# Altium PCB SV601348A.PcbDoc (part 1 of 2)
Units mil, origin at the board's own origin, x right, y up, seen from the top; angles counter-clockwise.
Board outline 3650 x 3650 mil, 6 copper layers (Top Layer, MidLayer1, MidLayer2, MidLayer3, MidLayer4, Bottom Layer), stack 60.8 mil thick; 120 components, 45 nets, 333 pads, 436 vias.
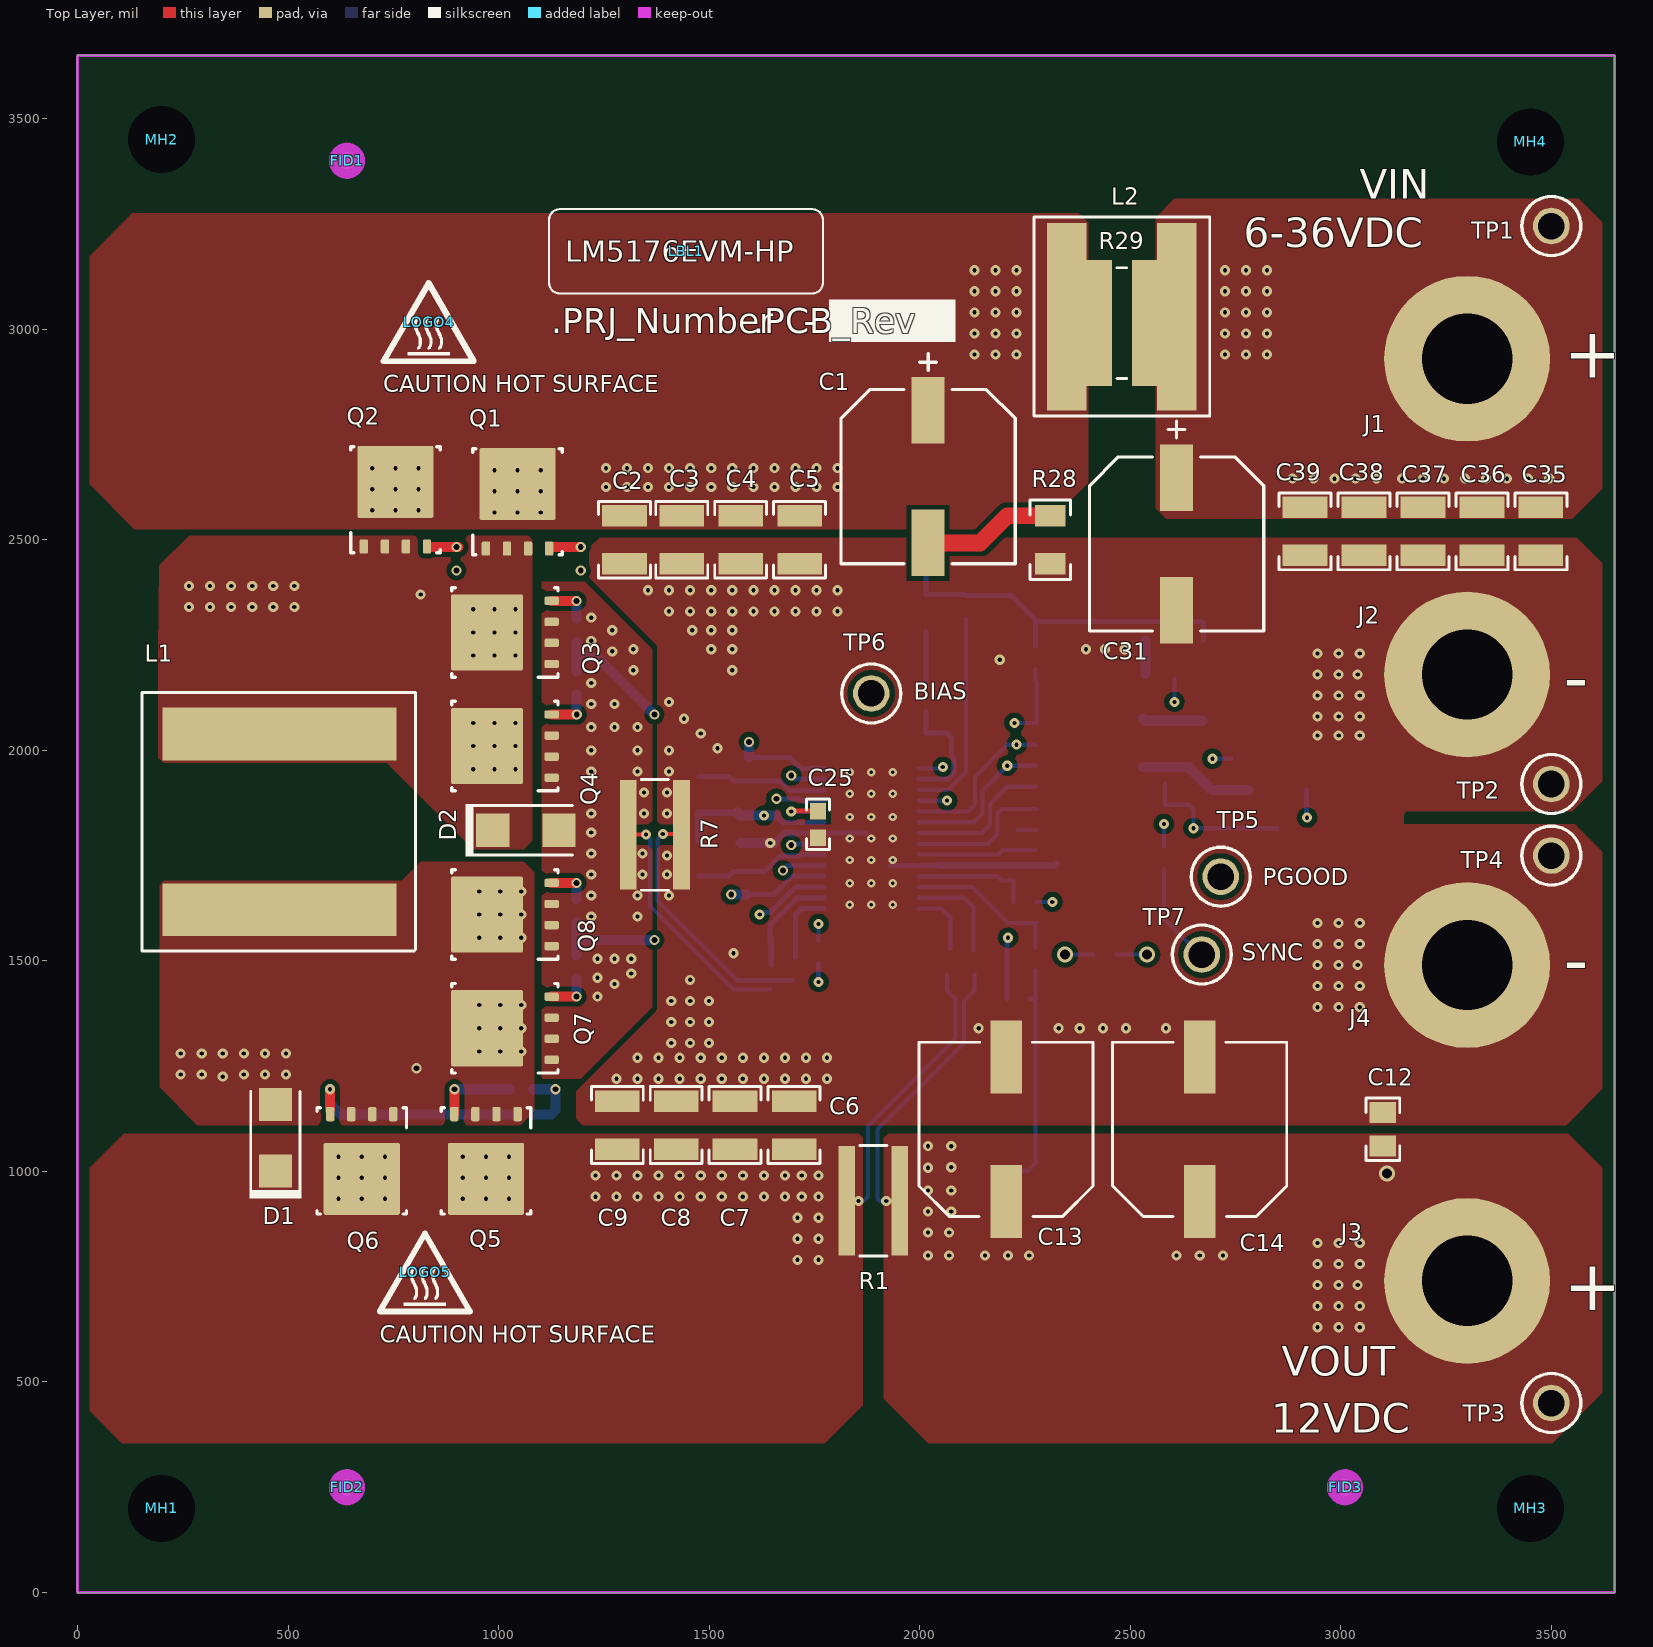
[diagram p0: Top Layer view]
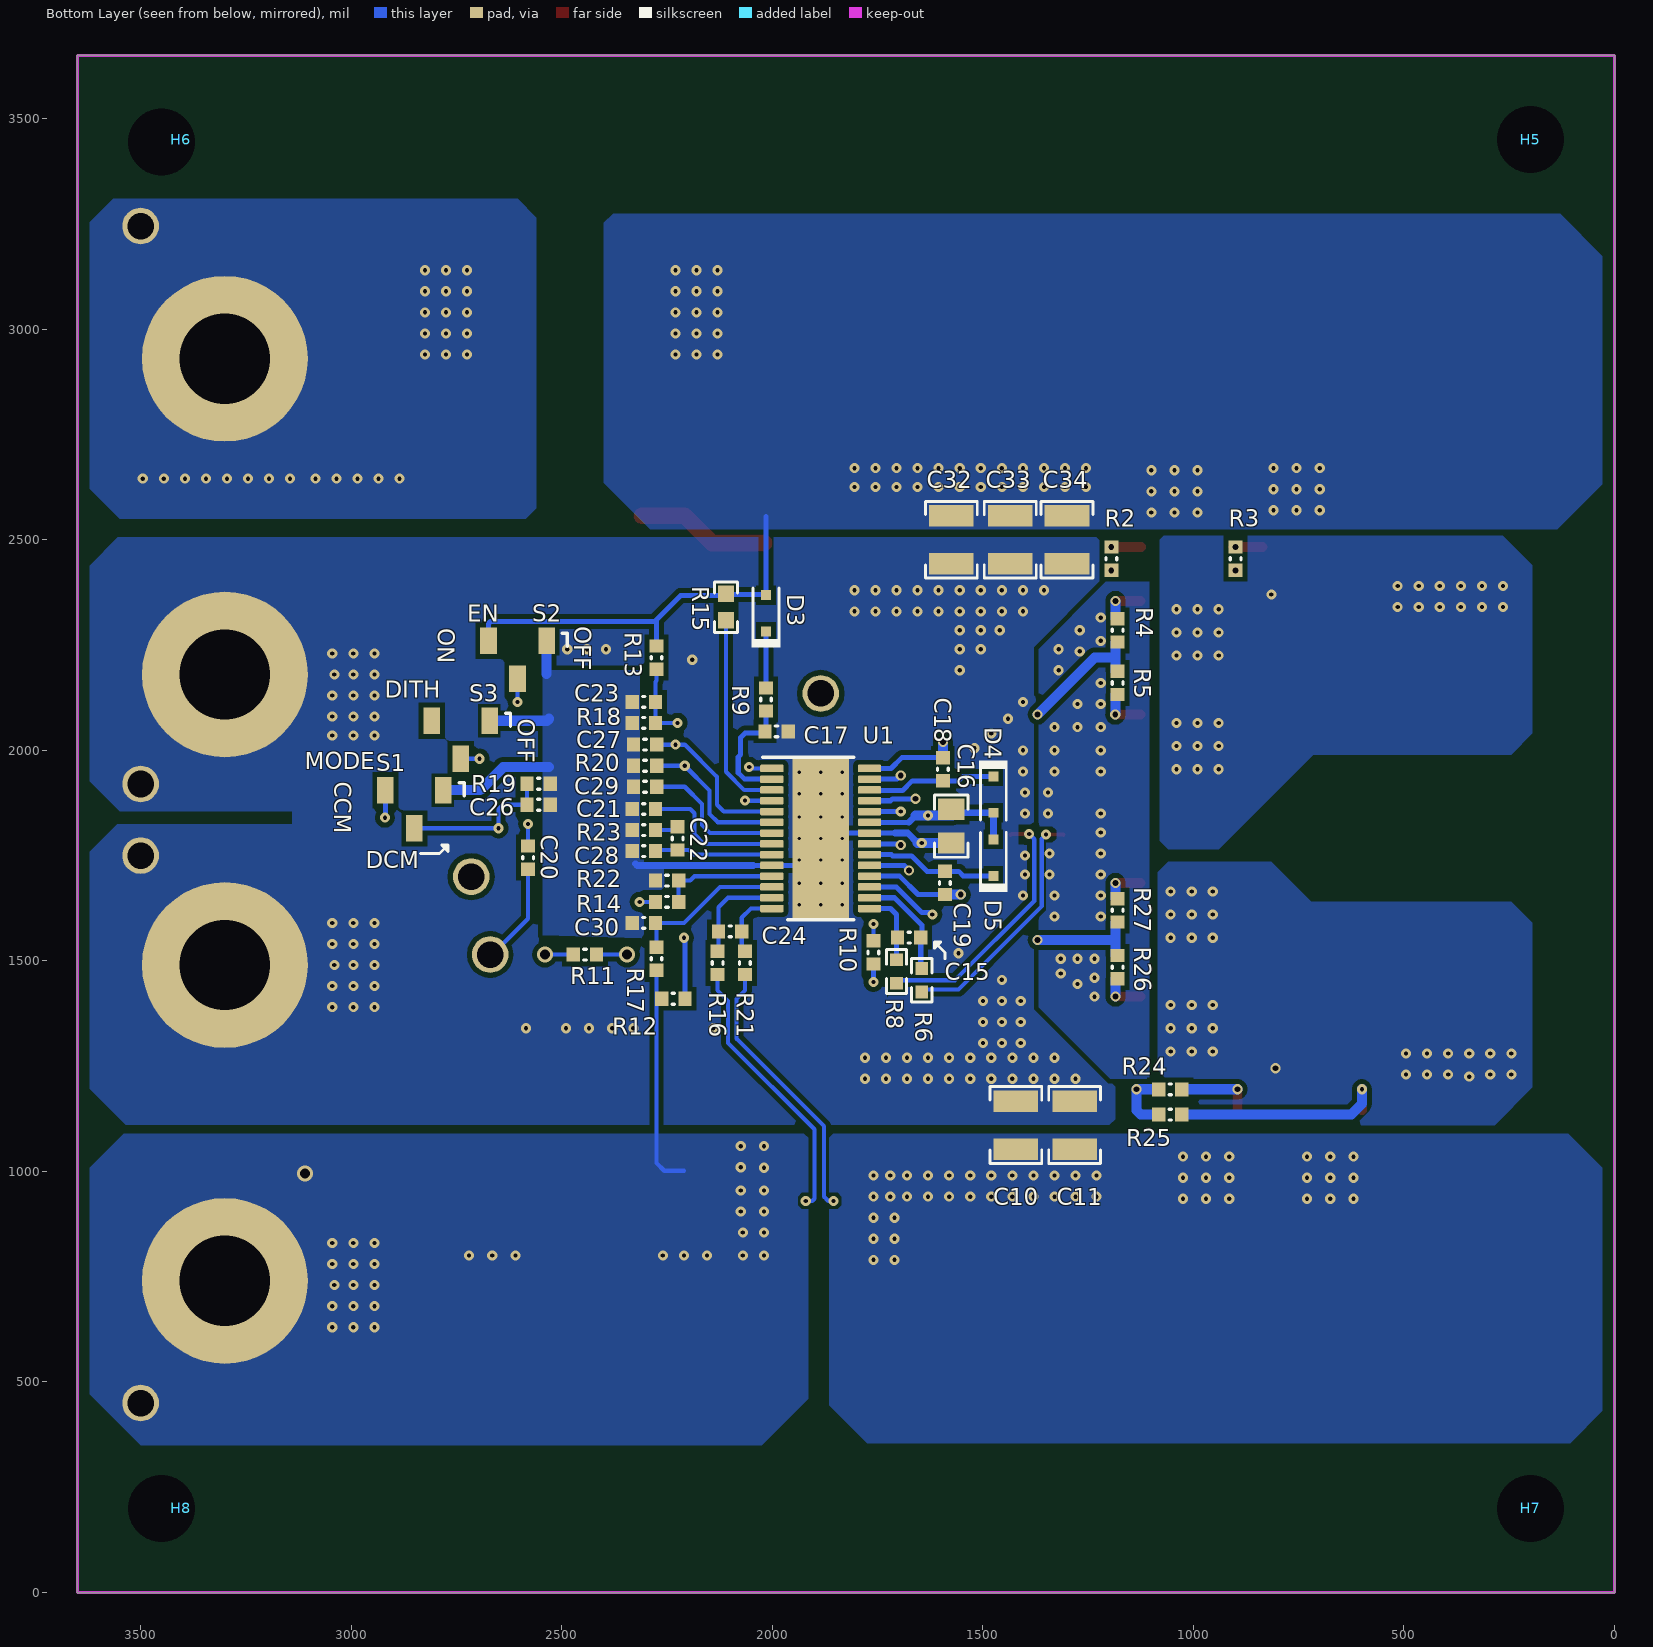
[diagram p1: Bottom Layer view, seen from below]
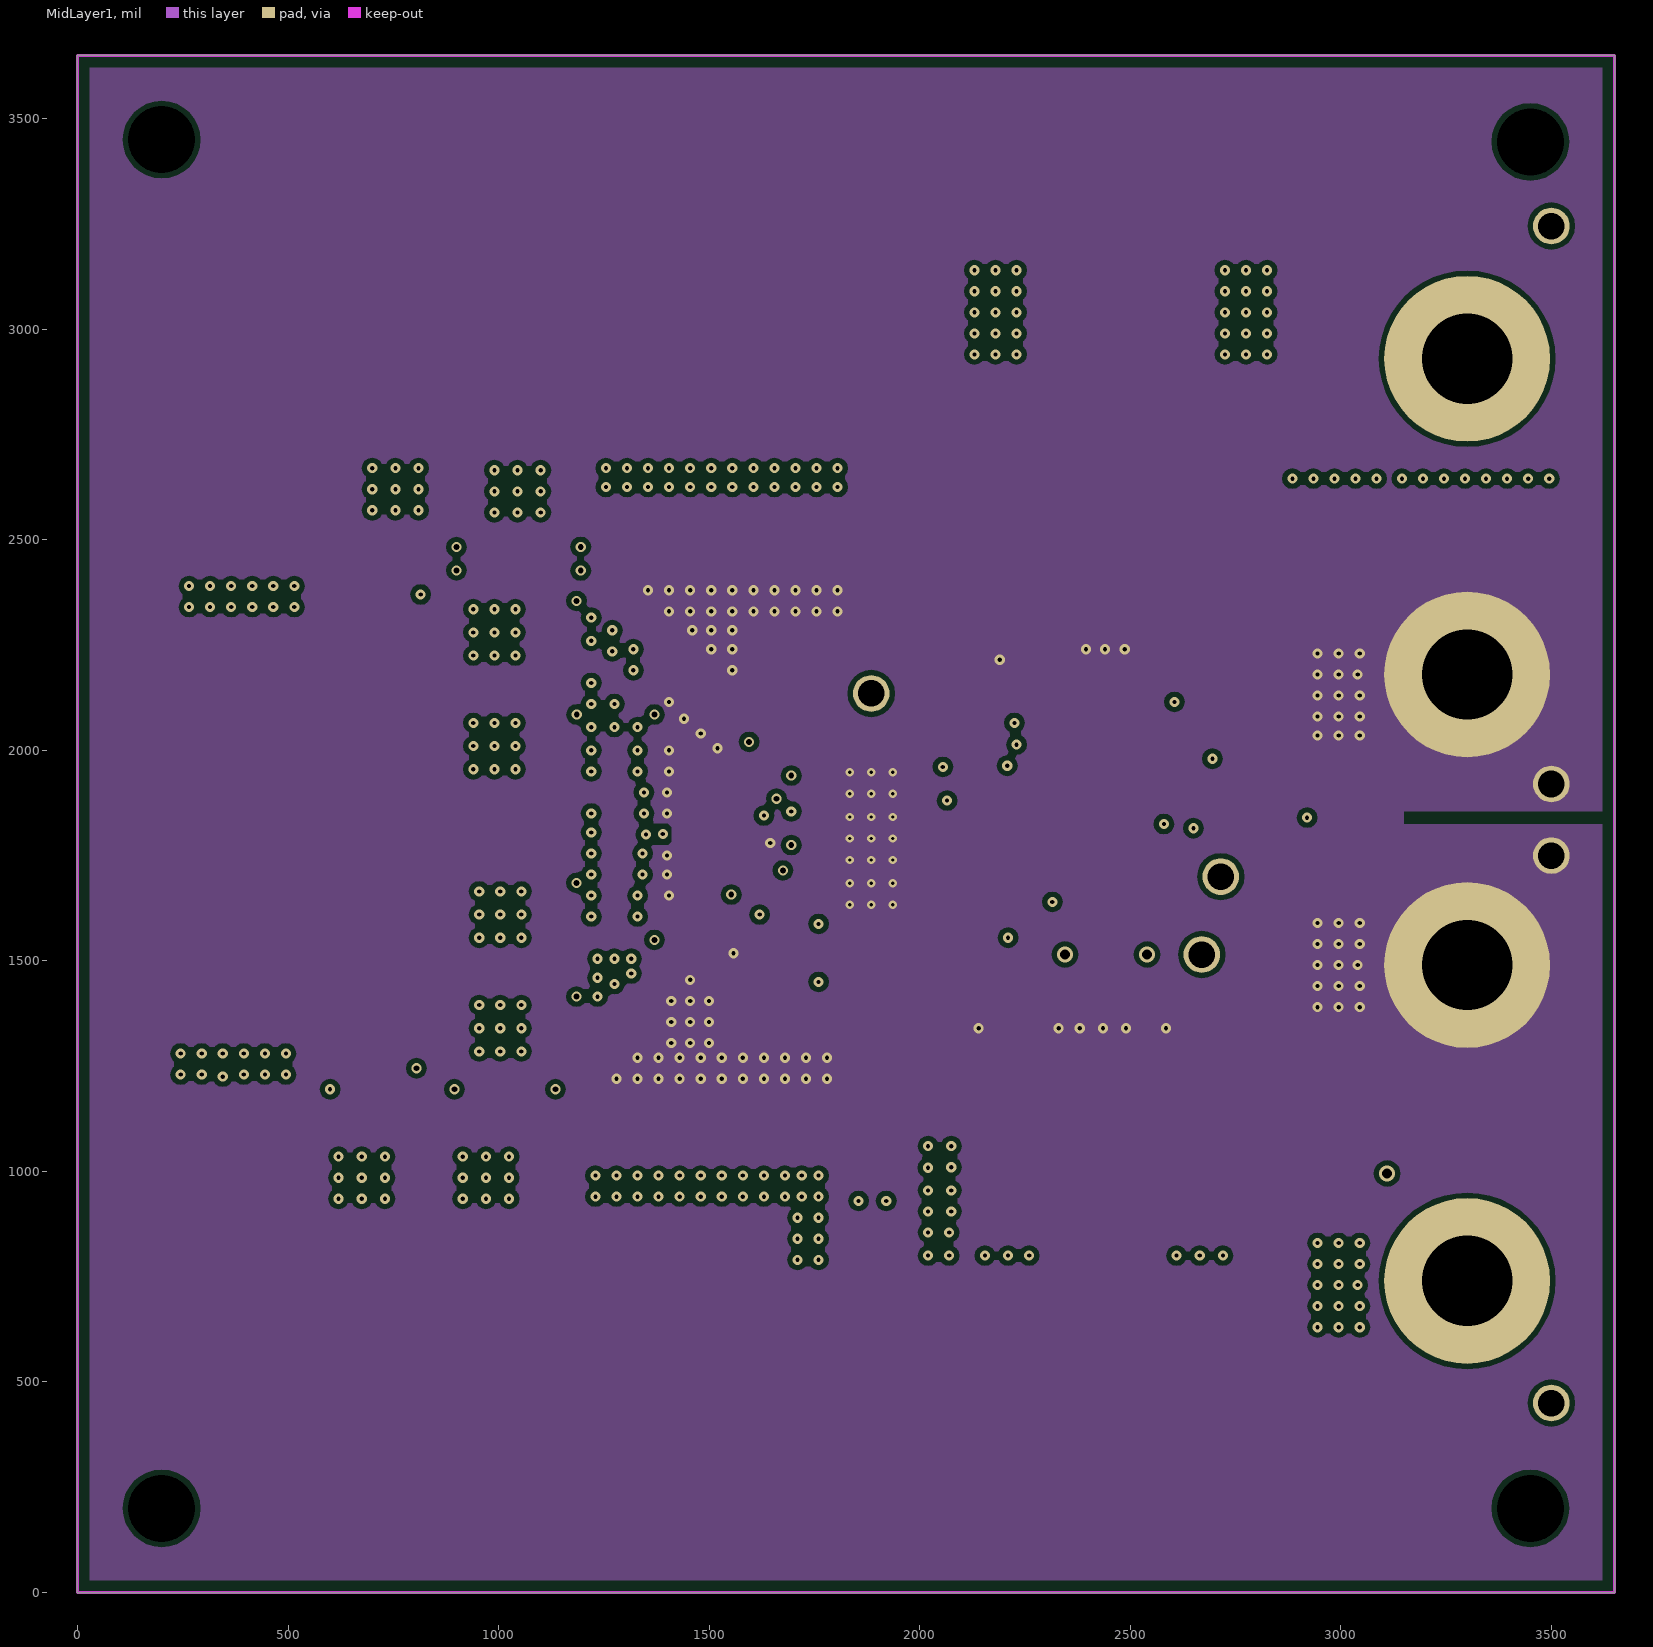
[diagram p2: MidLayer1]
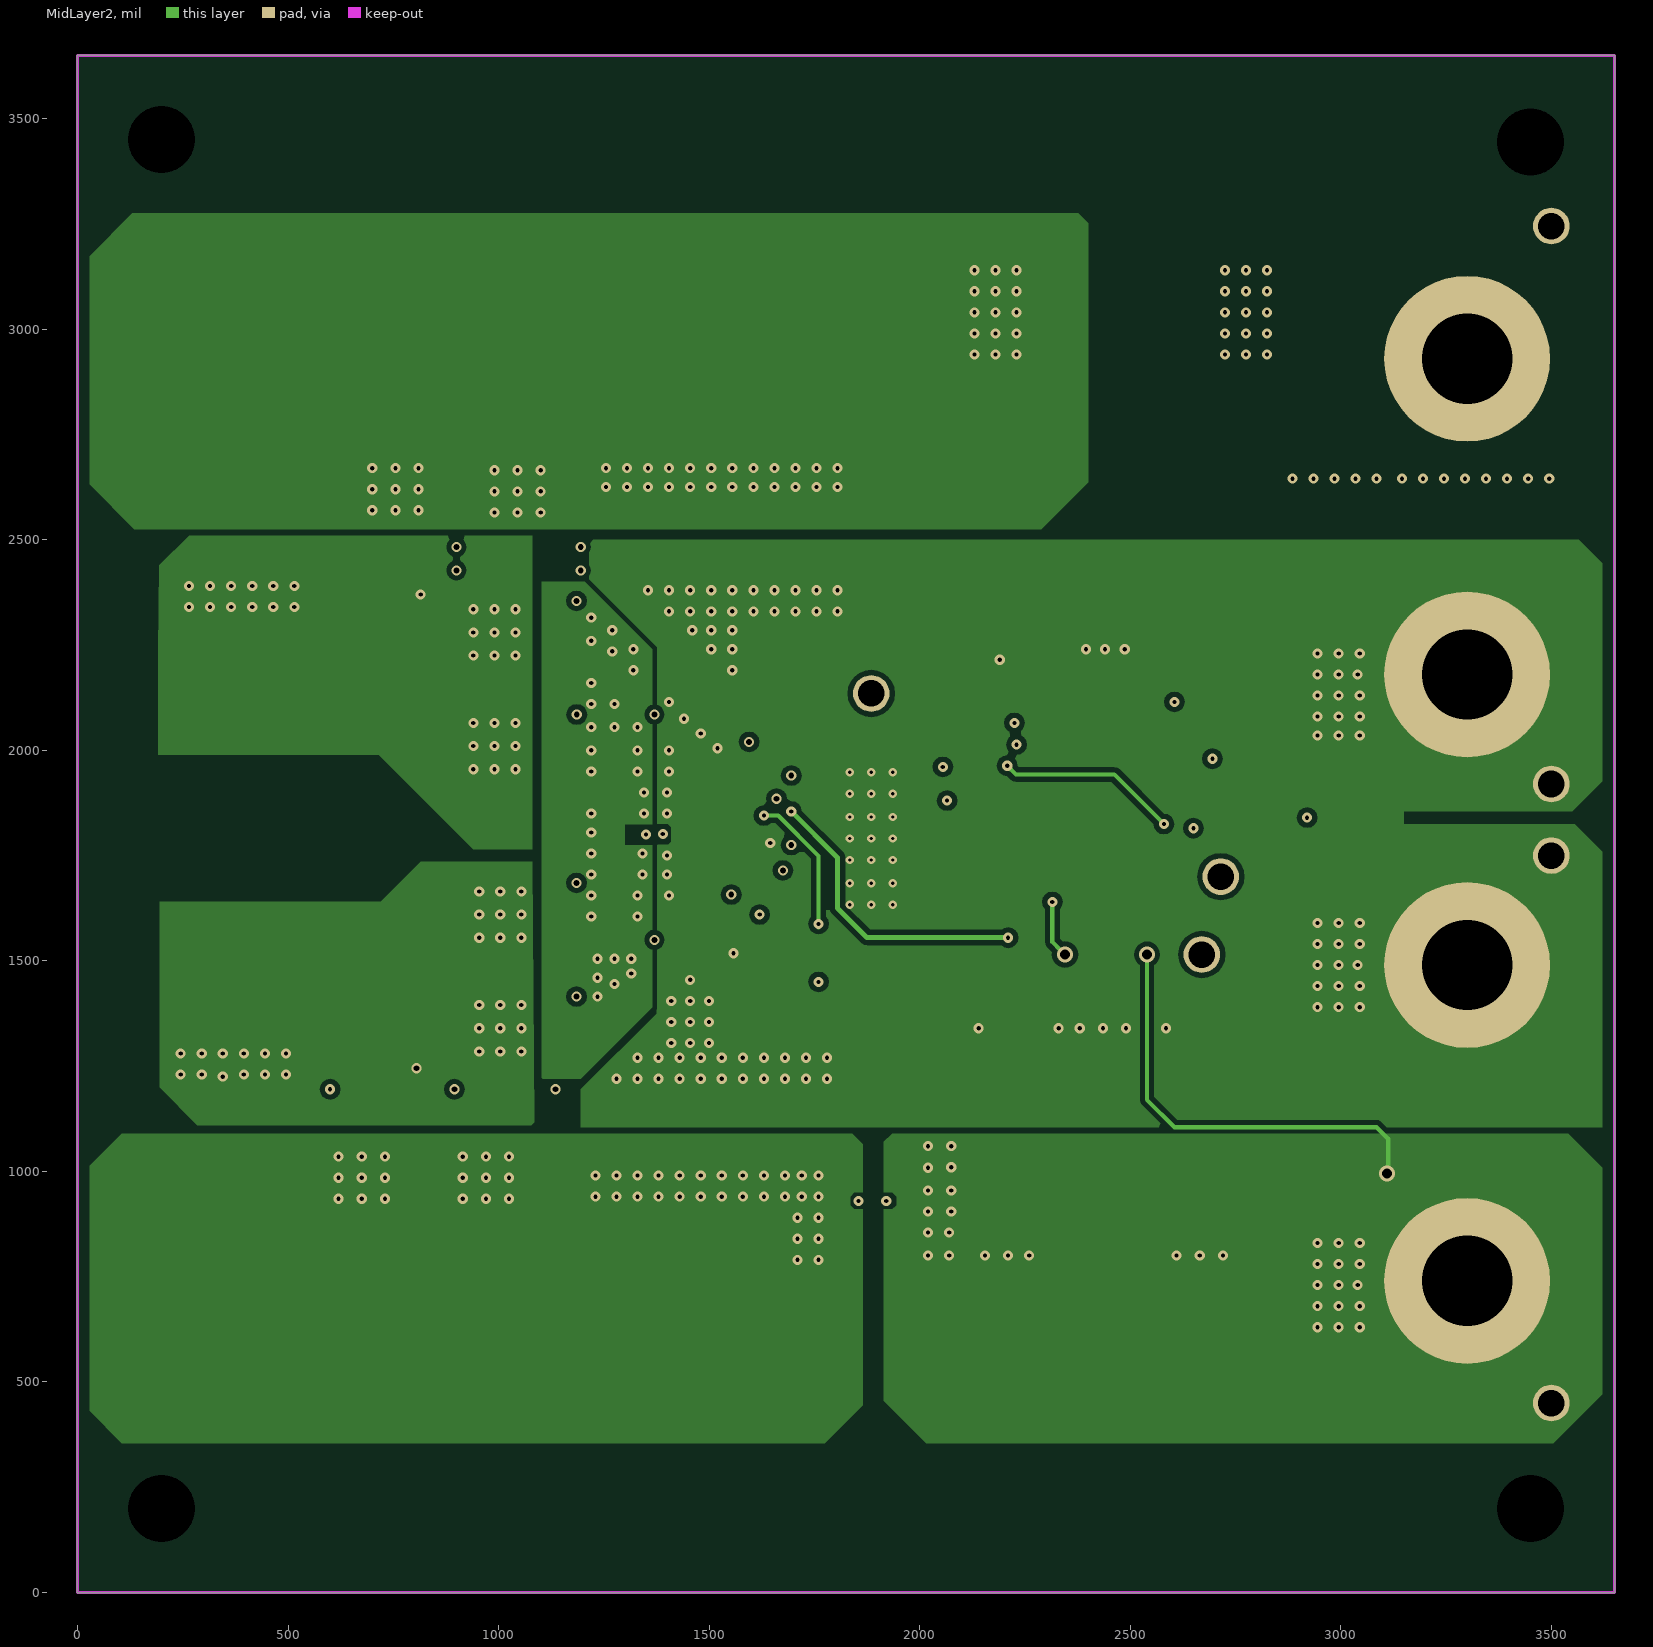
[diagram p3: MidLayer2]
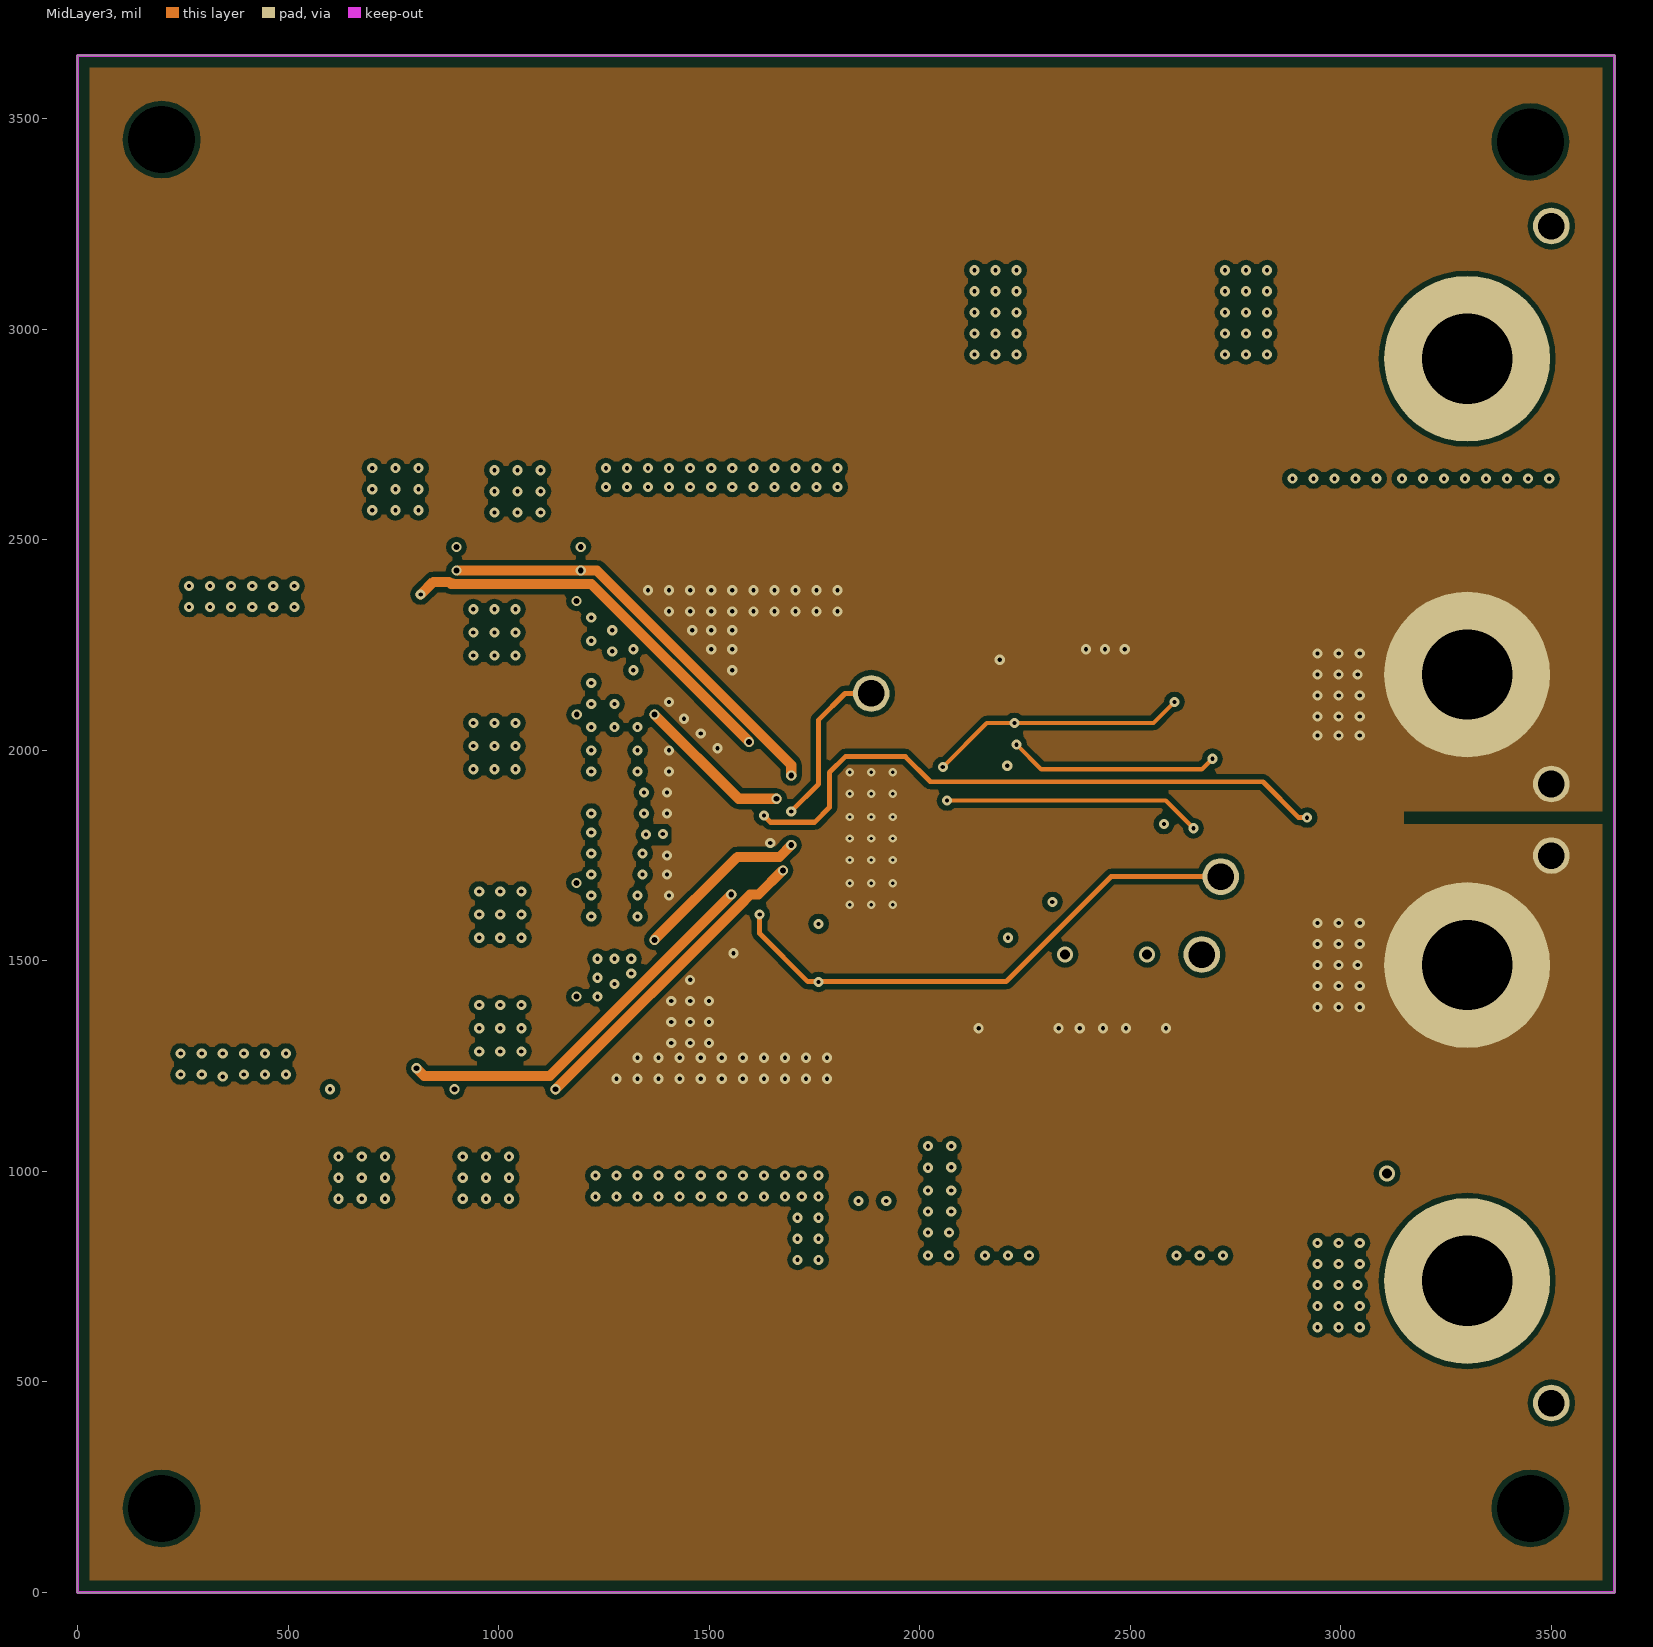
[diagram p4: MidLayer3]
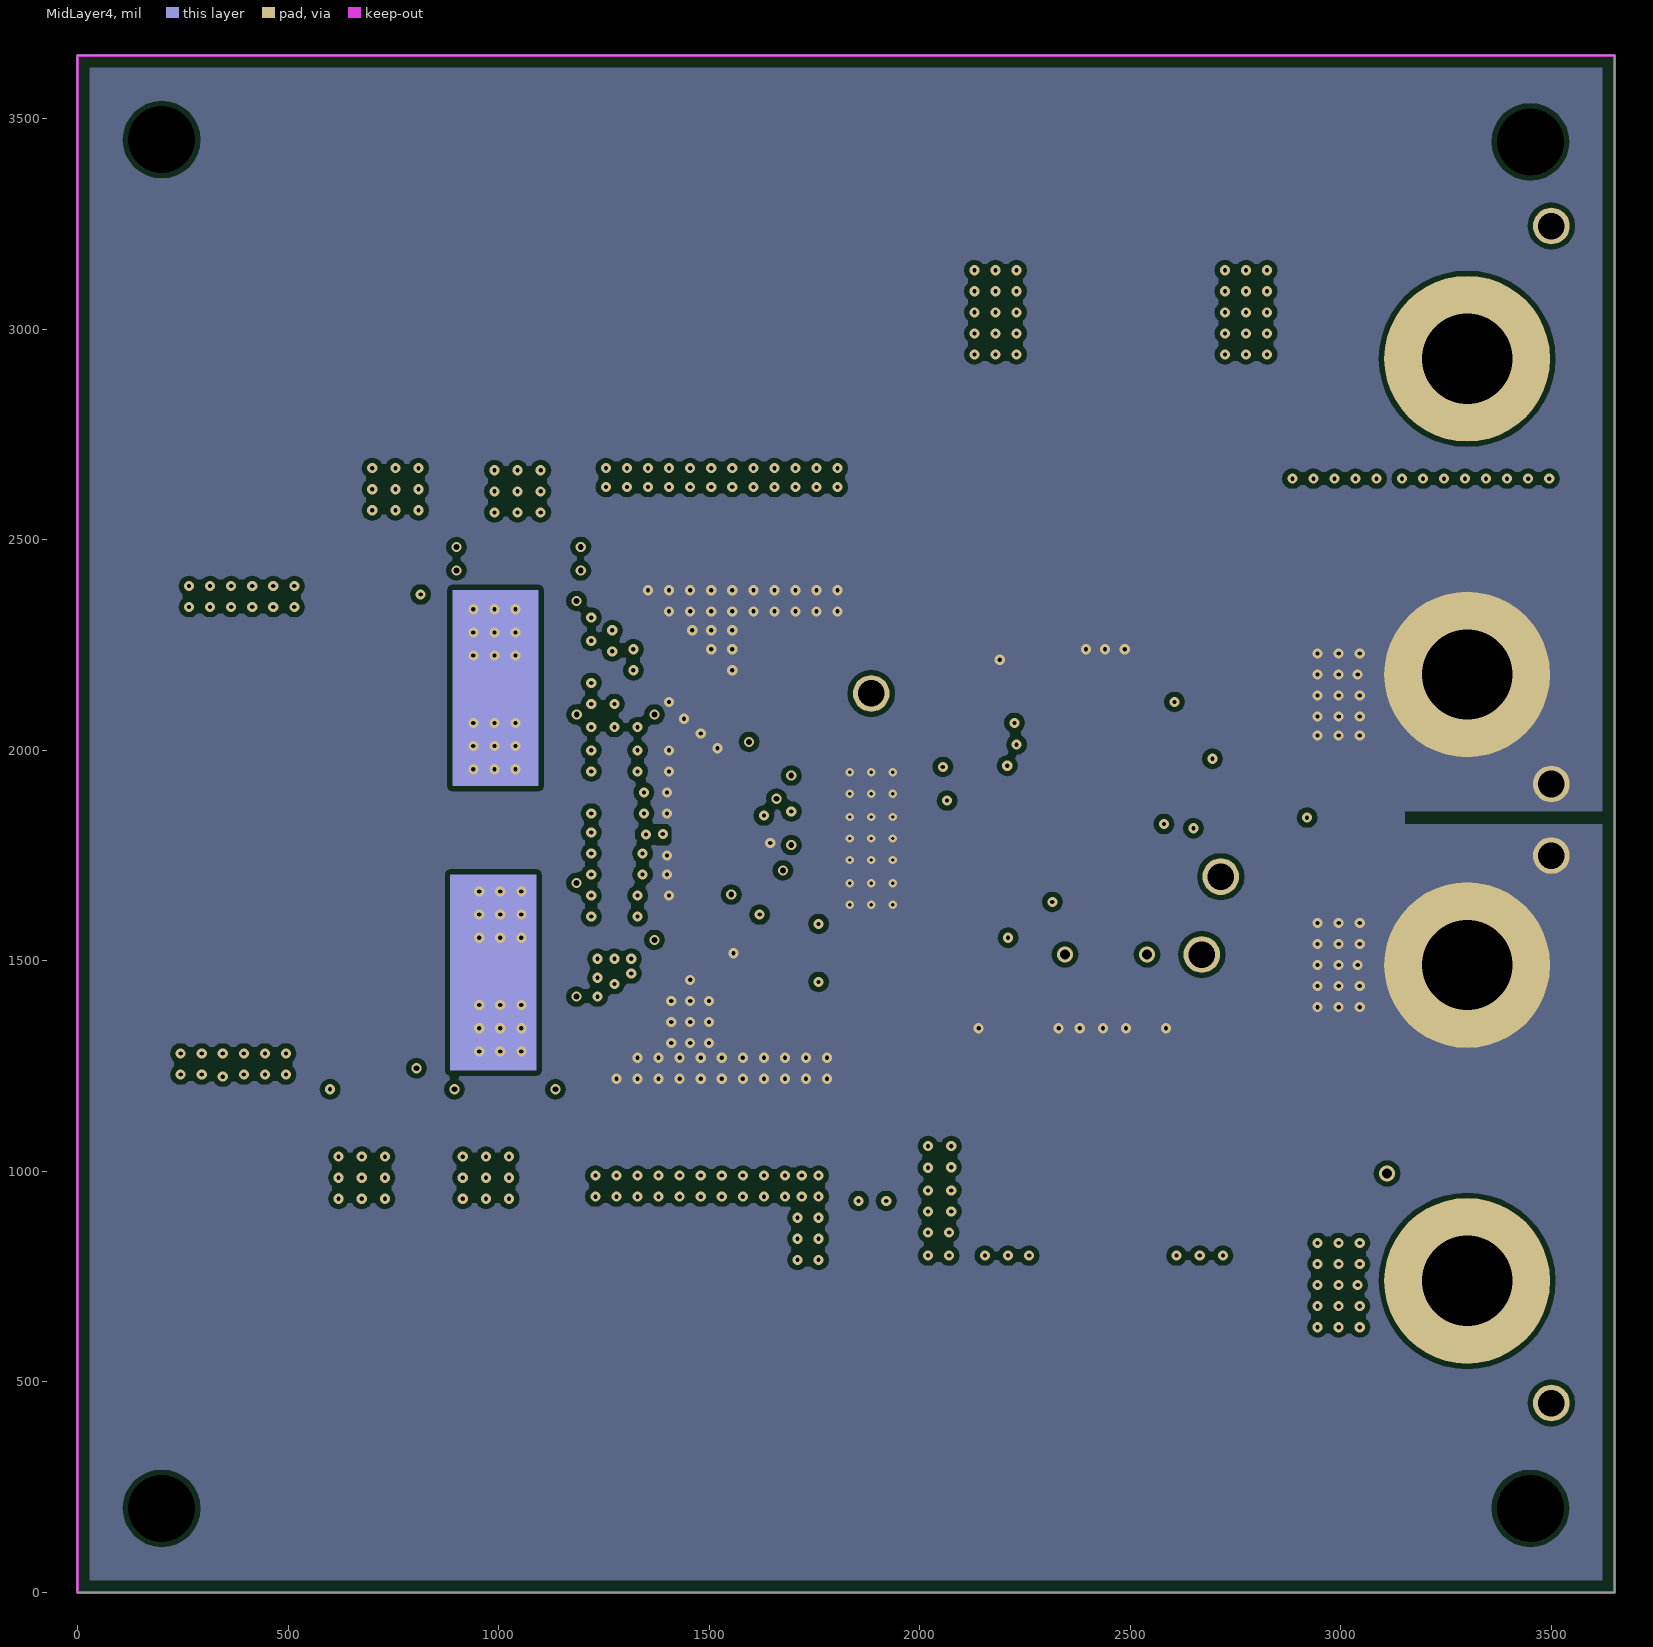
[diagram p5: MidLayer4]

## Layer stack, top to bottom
Top Solder: solder mask 0.4, Solder Resist, Dk 3.5
Top Layer: signal copper 2.8
Dielectric1: prepreg 8, FR-4, Dk 4.2
MidLayer1: signal copper 2.8
Dielectric2: prepreg 8, FR-4, Dk 4.8
MidLayer2: signal copper 2.8
Dielectric3: prepreg 12, FR-4, Dk 4.2
MidLayer3: signal copper 2.8
Dielectric4: prepreg 8, FR-4, Dk 4.8
MidLayer4: signal copper 2.8
Dielectric5: core 8, FR-4, Dk 4.8
Bottom Layer: signal copper 2.8
Bottom Solder: solder mask 0.4, Solder Resist, Dk 3.5

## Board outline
0,0 3650,0 3650,3650 0,3650

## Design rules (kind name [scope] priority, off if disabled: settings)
AcuteAngle [All] p1: minimum=4.50000000000000E+0001 checktracksonly=FALSE
AssemblyTestPointUsage [All] p1: valid=2
Clearance Clearance_BoardEdge_MountingHoles [OnCopper and InComponentClass('Mounting Holes') vs KeepOut] p1: gap=40 ignorepadtopadclearanceinfootprint=FALSE except(0: Arc-Hole Track-Hole SMDPad-Hole THPad-Hole Via-Hole Fill-Hole Poly-Hole Region-Hole Text-Hole)
Clearance Clearance_BoardEdge_Poly [OnCopper and InPoly vs KeepOut] p2: gap=25 ignorepadtopadclearanceinfootprint=FALSE except(0: Arc-Hole Track-Hole SMDPad-Hole THPad-Hole Via-Hole Fill-Hole Poly-Hole Region-Hole Text-Hole)
Clearance Clearance_BoardEdge [OnCopper and Not InComponentClass('Logo') and not InComponentClass('FiducialMark') and not InRegion(1000,500,4000,800) and Not IsKeepout vs KeepOut] p3: gap=47 ignorepadtopadclearanceinfootprint=FALSE except(0: Arc-Hole Track-Hole SMDPad-Hole THPad-Hole Via-Hole Fill-Hole Poly-Hole Region-Hole Text-Hole)
Clearance Clearance_Poly [InPolygon] p4: gap=12 ignorepadtopadclearanceinfootprint=FALSE except(0: Arc-Hole Track-Hole SMDPad-Hole THPad-Hole Via-Hole Fill-Hole Poly-Hole Region-Hole Text-Hole)
Clearance Clearance_FiducialMark [IsKeepOut and InComponentClass('FiducialMark') vs IsPad and InComponentClass('FiducialMark')] p5: gap=0 ignorepadtopadclearanceinfootprint=FALSE
Clearance [All] p6: gap=7.87 ignorepadtopadclearanceinfootprint=FALSE except(0: Arc-Hole Track-Hole SMDPad-Hole THPad-Hole Via-Hole Fill-Hole Poly-Hole Region-Hole Text-Hole)
ComponentClearance ComponentClearance_EMI-Shunt [InComponent('L2') vs InComponent('R29')] p1: gap=0 collisioncheckmode=3 verticalgap=0 showdistances=FALSE
ComponentClearance ComponentClearance_Shunt [InComponentClass('Header') vs InComponentClass('Shunt')] p2: gap=0 collisioncheckmode=3 verticalgap=0 showdistances=FALSE
ComponentClearance ComponentClearance_MountingHoles_FiducialMarks [InComponentClass('Mounting Holes') vs InComponentClass('FiducialMark')] p3: gap=42 collisioncheckmode=3 verticalgap=10 showdistances=FALSE
ComponentClearance ComponentClearance_Logo [InComponentClass('Logo')] p4: gap=50 collisioncheckmode=3 verticalgap=10 showdistances=FALSE
ComponentClearance ComponentClearance_ScrewToNut [(HasFootprint('NY PMS 440 0025 PH')) vs (HasFootprint('Keystone_1902C'))] p5: gap=5 collisioncheckmode=3 verticalgap=10 showdistances=FALSE
ComponentClearance ComponentClearance_MountingHoles [InComponentClass('Mounting Holes')] p6: gap=200 collisioncheckmode=3 verticalgap=100000 showdistances=FALSE
ComponentClearance ComponentClearance_SmallPassives [HasFootprint('0201*') or HasFootprint('0402*') or HasFootprint('0508') or HasFootprint('0603*') or HasFootprint('0612') or HasFootprint('0805*') or HasFootprint('0815*') or HasFootprint('0830*') or HasFootprint('1206*') or HasFootprint('1210*') or HasFootprint('1808*') or HasFootprint('1812*') or HasFootprint('1825*') or HasFootprint('2010*') or HasFootprint('2220*') or HasFootprint('2225*') or HasFootprint('2512*') or HasFootprint('2728*') or HasFootprint('3518*') vs HasFootprint('0201*') or HasFootprint('0402*') or HasFootprint('0508') or HasFootprint('0603*') or HasFootprint('0612') or HasFootprint('0805*') or HasFootprint('0815*') or HasFootprint('0830*') or HasFootprint('1206*') or HasFootprint('1210*') or HasFootprint('1808*') or HasFootprint('1812*') or HasFootprint('1825*') or HasFootprint('2010*') or HasFootprint('2220*') or HasFootprint('2225*') or HasFootprint('2512*') or HasFootprint('2728*') or HasFootprint('3518*')] p7: gap=10 collisioncheckmode=3 verticalgap=10 showdistances=FALSE
ComponentClearance ComponentClearance_THtoSMT [IsThruComponent vs IsSMTComponent] p8: gap=40 collisioncheckmode=3 verticalgap=30 showdistances=FALSE
ComponentClearance ComponentClearance_THtoTH [IsThruComponent vs IsThruComponent] p9: gap=25 collisioncheckmode=3 verticalgap=15 showdistances=FALSE
ComponentClearance [All] p10: gap=40 collisioncheckmode=3 verticalgap=10 showdistances=FALSE
DiffPairsRouting [All] p1: maxlimit=100 minlimit=10 mostfreqgap=10 toplayer_minwidth=15 toplayer_maxwidth=15 toplayer_prefwidth=15 midlayer1_minwidth=15 midlayer1_maxwidth=15 midlayer1_prefwidth=15 midlayer2_minwidth=15 midlayer2_maxwidth=15 midlayer2_prefwidth=15 midlayer3_minwidth=15 midlayer3_maxwidth=15 midlayer3_prefwidth=15 midlayer4_minwidth=15 midlayer4_maxwidth=15 midlayer4_prefwidth=15 bottomlayer_minwidth=15 bottomlayer_maxwidth=15 bottomlayer_prefwidth=15 maxuncoupledlength=1000
FabricationTestPointUsage TestPointUsage [All] p1: valid=2 allowmultiple=FALSE
FabricationTestpoint Testpoint [All] p1: side=3 testpointundercomponent=TRUE minsize=40 maxsize=100 preferedsize=60 minholesize=0 maxholesize=40 preferedholesize=32 testpointgrid=1 allowsidetop=TRUE allowsidebottom=TRUE usegrid=TRUE gridtolerance=0.01
FanoutControl Fanout_LCC [IsLCC] p1: bgadir=Out bgaviamode=Centered fanoutstyle=Auto fanoutdirection=Alternating viagrid=1 // Fanout_LCC (Default Rule)
FanoutControl Fanout_BGA [IsBGA] p2: bgadir=Out bgaviamode=Centered fanoutstyle=Auto fanoutdirection=Alternating viagrid=1 // Fanout_BGA (Default Rule)
FanoutControl Fanout_Default [All] p4: bgadir=Out bgaviamode=Centered fanoutstyle=Auto fanoutdirection=Alternating viagrid=1 // Fanout_Default (Default Rule)
FanoutControl Fanout_Small [(CompPinCount < 5)] p5: bgadir=Out bgaviamode=Centered fanoutstyle=Auto fanoutdirection=OutThenIn viagrid=1 // Fanout_Small (Default Rule)
HoleSize [All] p1: absolutevalues=TRUE maxlimit=280 minlimit=7.87 maxpercent=80.000 minpercent=20.000
MinimumAnnularRing MinimumAnnularRing_ThermalPadVias [IsVia and InAnyComponent] p1: minimumring=3.94
MinimumAnnularRing [All] p2: minimumring=5
MinimumSolderMaskSliver MinimumSolderMaskSliver_FET [HasFootprint('DNK0008A')] p1: minsoldermaskwidth=0
MinimumSolderMaskSliver MinimumSolderMaskSliver_Logo [InComponentClass('Logo') vs InComponentClass('Logo')] p2: minsoldermaskwidth=0.7
MinimumSolderMaskSliver [All] p3: minsoldermaskwidth=3.94
PlaneConnect [All] p1: planeconnectstyle=Relief reliefexpansion=10 reliefentries=4 reliefconductorwidth=10 reliefairgap=10
PolygonConnect [All] p1: connectstyle=Direct reliefconductorwidth=10 reliefentries=4 polygonreliefangle="90 Angle" airgapwidth=10
RoutingVias ThermalPadVias [IsVia and InAnyComponent] p1: holewidth=7.87 width=19.68 viastyle="Through Hole" minholewidth=7.87 minwidth=15.75 maxholewidth=12.99 maxwidth=23.62
RoutingVias [All] p2: holewidth=10 width=24 viastyle="Through Hole" minholewidth=7.87 minwidth=13.78 maxholewidth=40 maxwidth=65
SMDToCorner [All] p1: distance=30000
SilkToBoardRegionClearance [NOT ((IsComment OR IsDesignator) AND (Hide <> 'FAIL')) AND NOT InRegion (100,500,4000,800)] p1:
SilkToSilkClearance SilkToSilkClearance_PbFree [HasFootprint('Pb-Free_Overlay_Small')] p1: silktosilkclearance=0
SilkToSilkClearance [All] p2: silktosilkclearance=5
SilkToSolderMaskClearance SilkscreenOverComponentPads [IsPad] p1: minsilkscreentomaskgap=5 clearancetoexposedcopper=TRUE
SolderMaskExpansion [All] p1: expansion=1.97
Width [All] p1: maxlimit=100 minlimit=6 preferedwidth=10 checkconnectedcopper=TRUE
15 further rules are at their usual default settings.

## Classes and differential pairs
component class SV601348A-HW: FID1 FID2 FID3 H5 H6 H7 H8 LBL1 LOGO4 LOGO5 MH1 MH2 MH3 MH4 ZZ1 ZZ2 ZZ3 ZZ4 ZZ5 ZZ6 ZZ7 ZZ8
component class FiducialMark: FID1 FID2 FID3
component class AssemblyNote: ZZ1 ZZ2 ZZ3 ZZ4 ZZ5 ZZ6 ZZ7 ZZ8
component class Label: LBL1
component class SV601348A: C1 C2 C3 C4 C5 C6 C7 C8 C9 C10 C11 C12 C13 C14 C15 C16 C17 C18 C19 C20 C21 C22 C23 C24 C25 C26 C27 C28 C29 C30 C31 C32 C33 C34 C35 C36 C37 C38 C39 D1 D2 D3 D4 D5 J1 J2 J3 J4 L1 L2 Q1 Q2 Q3 Q4 Q5 Q6 Q7 Q8 R1 R2 R3 R4 R5 R6 R7 R8 R9 R10 R11 R12 R13 R14 R15 R16 R17 R18 R19 R20 R21 R22 R23 R24 R25 R26 R27 R28 R29 S1 S2 S3 TP1 TP2 TP3 TP4 TP5 TP6 TP7 U1

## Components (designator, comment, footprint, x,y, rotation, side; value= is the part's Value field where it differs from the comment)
C1 "PCR1J101MCL1GS" CR_1000x1270 2020,2650 r270 top value=100uF
C2 "GRM32ER71K475KE14L" 1210_270 1298.7,2500 r270 top value=4.7uF
C3 "GRM32ER71K475KE14L" 1210_270 1435,2500 r270 top value=4.7uF
C4 "GRM32ER71K475KE14L" 1210_270 1575,2500 r270 top value=4.7uF
C5 "GRM32ER71K475KE14L" 1210_270 1715,2500 r270 top value=4.7uF
C6 "GRM32ER71E226KE15L" 1210_270 1701.85,1110 r90 top value=22uF
C7 "GRM32ER71E226KE15L" 1210_270 1561.54,1110 r90 top value=22uF
C8 "GRM32ER71E226KE15L" 1210_270 1421.85,1110 r90 top value=22uF
C9 "GRM32ER71E226KE15L" 1210_270 1281.85,1110 r90 top value=22uF
C10 "GRM32ER71E226KE15L" 1210_270 1421.85,1110 r90 bottom value=22uF
C11 "GRM32ER71E226KE15L" 1210_270 1281.85,1110 r90 bottom value=22uF
C12 "GRM219R71E105KA88D" 0805_HV 3100,1100 r90 top value=1uF
C13 "16SVP330M" SM_RADIAL_10AMM 2205,1100 r90 top value=330uF
C14 "16SVP330M" SM_RADIAL_10AMM 2665,1100 r90 top value=330uF
C15 "GRM1885C1H470JA01D" 0603L 1675,1555 r0 bottom value=47pF
C16 "GRM21BR71C475KA73L" 0805_HV 1575,1820 r90 bottom value=4.7uF
C17 "GRM188R72A104KA35D" 0603L 1990,2045 r180 bottom value=0.1uF
C18 "GRM188R71E224KA88D" 0603L 1595,1955 r270 bottom value=0.22uF
C19 "GRM188R71E224KA88D" 0603L 1590,1685 r270 bottom value=0.22uF
C20 "GRM1885C2A101JA01D" 0603L 2580,1745 r90 bottom value=100pF
C21 "GRM188R72A104KA35D" 0603L 2305,1860.63 r0 bottom value=0.1uF
C22 "GRM188R71H333KA61D" 0603L 2225,1790.63 r90 bottom value=0.033uF
C23 "47pF" 0603L 2305,2115 r0 bottom
C24 "GRM188R71C334KA01D" 0603L 2100,1570 r180 bottom value=0.33uF
C25 "GRM188R71E224KA88D" 0603 1758.62,1824.19 r270 top value=0.22uF
C26 "47pF" 0603L 2555,1870.63 r180 bottom
C27 "C0603C223K5RACTU" 0603L 2302.2,2013.43 r0 bottom value=0.022uF
C28 "GRM1885C2A102JA01D" 0603L 2305,1760.63 r0 bottom value=1000pF
C29 "GRM1885C1H271JA01D" 0603L 2302.2,1913.43 r0 bottom value=270pF
C30 "GRM1885C2A101JA01D" 0603L 2305,1590 r0 bottom value=100pF
C31 "PCR1J101MCL1GS" CR_1000x1270 2610,2490 r270 top value=100uF
C32 "GRM32ER71K475KE14L" 1210_270 1575,2500 r270 bottom value=4.7uF
C33 "GRM32ER71K475KE14L" 1210_270 1435,2500 r270 bottom value=4.7uF
C34 "GRM32ER71K475KE14L" 1210_270 1300,2500 r270 bottom value=4.7uF
C35 "GRM32ER71K475KE14L" 1210_270 3475,2520 r270 top value=4.7uF
C36 "GRM32ER71K475KE14L" 1210_270 3335,2520 r270 top value=4.7uF
C37 "GRM32ER71K475KE14L" 1210_270 3195,2520 r270 top value=4.7uF
C38 "GRM32ER71K475KE14L" 1210_270 3055,2520 r270 top value=4.7uF
C39 "GRM32ER71K475KE14L" 1210_270 2915,2520 r270 top value=4.7uF
D1 "20V" SMA 470,1080 r90 top
D2 "60V" SMA 1065,1810 r0 top
D3 "60V" SOD-323F 2015,2325 r90 bottom
D4 "100V" sod-323 1475,1895 r270 bottom
D5 "100V" sod-323 1475,1745 r90 bottom
FID1 "Fiducial" Fiducial10-20 640,3400 r0 top
FID2 "Fiducial" Fiducial10-20 640,250 r0 top
FID3 "Fiducial" Fiducial10-20 3010,250 r0 top
H5 "1902C" Keystone_1902C 200,3450 r180 bottom locked
H6 "1902C" Keystone_1902C 3405,3450 r180 bottom locked
H7 "1902C" Keystone_1902C 200,200 r180 bottom locked
H8 "1902C" Keystone_1902C 3405,200 r180 bottom locked
J1 "575-8" Keystone575-8 3300,2930 r90 top
J2 "575-8" Keystone575-8 3300,2180 r90 top
J3 "575-8" Keystone575-8 3300,740 r90 top
J4 "575-8" Keystone575-8 3300,1490 r90 top
L1 "XAL1510-682MEB" XAL1510 480,1830 r270 top value=6.8uH
L2 "XAL1010-222MEB" XAL1010 2480,3030 r180 top value=2.2uH
LBL1 "LM5176EVM-HP" Label_650x200 1445,3185 r0 top
LOGO4 "CAUTION HOT SURFACE" IEC_HotSurface_Small 834,3017 r0 top
LOGO5 "CAUTION HOT SURFACE" IEC_HotSurface_Small 825,760 r0 top
MH1 "MTG_NoPads" MTG_159mil 200,200 r0 top
MH2 "MTG_NoPads" MTG_159mil 200,3450 r0 top
MH3 "MTG_NoPads" MTG_159mil 3450,200 r0 top
MH4 "MTG_NoPads" MTG_159mil 3450,3445 r0 top
Q1 "CSD18532Q5B" DNK0008A 1045,2590 r90 top value=60V
Q2 "CSD18532Q5B" DNK0008A 755,2595 r90 top value=60V
Q3 "CSD18532Q5B" DNK0008A 1015,2280 r180 top value=60V
Q4 "CSD18532Q5B" DNK0008A 1015,2010 r180 top value=60V
Q5 "CSD17573Q5B" DNK0008A 970,1025 r270 top value=30V
Q6 "CSD17573Q5B" DNK0008A 675,1025 r270 top value=30V
Q7 "CSD17573Q5B" DNK0008A 1015,1340 r180 top value=30V
Q8 "CSD17573Q5B" DNK0008A 1015,1610 r180 top value=30V
R1 "KRL6432E-M-R004-F-T1" 2512_WIDE 1890,930 r0 top value=0.004
R2 "RC0603JR-070RL" 0603L 1195,2455 r270 bottom value=0
R3 "RC0603JR-070RL" 0603L 900,2455 r270 bottom value=0
R4 "RC0603JR-070RL" 0603L 1180,2285 r270 bottom value=0
R5 "RC0603JR-070RL" 0603L 1180,2160 r90 bottom value=0
R6 "RC0603FR-07100RL" 0603_HV 1645,1454 r270 bottom value=100
R7 "KRL6432E-M-R004-F-T1" 2512_WIDE 1371.36,1799.47 r180 top value=0.004
R8 "RC0603FR-07100RL" 0603_HV 1705,1475 r270 bottom value=100
R9 "RC0603FR-0710RL" 0603L 2015,2120.63 r90 bottom value=10.0
R10 "RC0603FR-0710KL" 0603L 1760,1520 r90 bottom value=10.0k
R11 "RC0603FR-0710RL" 0603L 2445,1515 r180 bottom value=10.0
R12 "RC0603JR-070RL" 0603L 2235,1410 r180 bottom value=0
R13 "RC0603FR-07249KL" 0603L 2275,2220 r90 bottom value=249k
R14 "RC0603FR-07280KL" 0603L 2250,1640 r0 bottom value=280k
R15 "CRCW06032K00FKEA" 0603 2110,2340 r90 bottom value=2.00k
R16 "100" 0603L 2130,1495 r270 bottom
R17 "RC0603JR-070RL" 0603L 2275,1505 r90 bottom value=0
R18 "RC0603FR-0759KL" 0603L 2305,2065 r180 bottom value=59.0k
R19 "RC0603FR-0793K1L" 0603L 2555,1920.63 r0 bottom value=93.1k
R20 "CRCW060333K2FKEA" 0603L 2302.2,1963.43 r180 bottom value=33.2k
R21 "100" 0603L 2065,1495 r270 bottom
R22 "RC0603FR-0720KL" 0603L 2249.94,1690.63 r180 bottom value=20.0k
R23 "CRCW06036K19FKEA" 0603L 2305,1810.63 r180 bottom value=6.19k
R24 "RC0603JR-070RL" 0603L 1055,1195 r0 bottom value=0
R25 "RC0603JR-070RL" 0603L 1055,1135 r0 bottom value=0
R26 "RC0603JR-070RL" 0603L 1180,1485 r90 bottom value=0
R27 "RC0603JR-070RL" 0603L 1180,1620 r270 bottom value=0
R28 "CRCW12060000Z0EA" 1206 2310,2500 r90 top value=0
R29 "RCL12250000Z0EG" 2512_WIDE_VISHAY 2480,3015 r180 top value=0
S1 "CJS-1201TA" SW_CJS_1201A 2850,1860 r0 bottom
S2 "CJS-1201TA" SW_CJS_1201A 2605,2215 r0 bottom
S3 "CJS-1201TA" SW_CJS_1201A 2740,2025 r0 bottom
TP1 "5005" Keystone5005 3500,3245 r90 top value=Red
TP2 "5006" Keystone5006 3500,1920 r90 top value=Black
TP3 "5005" Keystone5005 3500,450 r90 top value=Red
TP4 "5006" Keystone5006 3500,1750 r90 top value=Black
TP5 "PGOOD" Keystone5007 2715,1700 r90 top
TP6 "BIAS" Keystone5007 1885,2135 r90 top value=White
TP7 "SYNC" Keystone5007 2670,1515 r90 top value=White
U1 "LM5176PWPR" PWP0028C_N 1885,1790.63 r180 bottom
ZZ1 "This Assembly Note is for PCB labels only" AssemblyNoteLabel -95,4653 r0 top
ZZ2 "These assemblies are ESD sensitive, ESD precautions shall be observed." AssemblyNote -95,4547.86 r0 top
ZZ3 "These assemblies must be clean and free from flux and all contaminants. Use of no clean flux is not acceptable." AssemblyNote -95,4463.05 r0 top
ZZ4 "These assemblies must comply with workmanship standards IPC-A-610 Class 2, unless otherwise specified." AssemblyNote -95,4378.24 r0 top
ZZ5 "Remove Kapton tape from switches S1 thru S3 on PCB Bottom side after final wash." AssemblyNote -95,4293.43 r0 top
ZZ6 "Set S1 switch to 'CCM' position as per silkscreen label" AssemblyNote -95,4208.62 r0 top
ZZ7 "Set S2 switch to Center position" AssemblyNote -95,4123.81 r0 top
ZZ8 "Set S3 switch to 'OFF' position per silk screen label." AssemblyNote -95,4039 r0 top

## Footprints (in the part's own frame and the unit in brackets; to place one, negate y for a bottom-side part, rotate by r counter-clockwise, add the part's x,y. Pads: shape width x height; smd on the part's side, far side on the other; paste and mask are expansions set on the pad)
0603 [mm] "0603 from SM-752 data"
  rect 1x0.95 smd: 1(-0.8,0) 2(0.8,0)
  silkscreen extent -1.52,-0.69 1.52,0.69, body extent -0.87,-0.47 0.87,0.47, height 1
0603_HV [mil] "Ernesto recommended land pattern.  26 mil between pads."
  rect 30x30 smd: 1(-28,0) 2(28,0)
  silkscreen extent -52,-24 52,24, body extent -34,-19 34,19, height 39
0603L [mm] "0603 from SM-752 data"
  rect 0.8x0.85 smd: 1(-0.7,0) 2(0.7,0)
  silkscreen extent -0.07,-0.33 0.07,0.33, body extent -0.87,-0.47 0.87,0.47, height 1
0805_HV [mil] "0805 with 30mil clearance between pads"
  rect 50x63 smd: 1(-40,0) 2(40,0)
  silkscreen extent -74,-40 74,40, body extent -43,-29 43,29, height 57
1206 [mm] "1206 from SM-752 data"
  rect 1.3x1.85 smd: 1(-1.45,0) 2(1.45,0)
  silkscreen extent -2.4,-1.21 2.4,1.21, body extent -1.7,-0.9 1.7,0.9, height 1.35
1210_270 [mm] "1210"
  rect 1.3x2.7 smd: 1(-1.45,0) 2(1.45,0)
  silkscreen extent -2.32,-1.57 2.32,1.57, body extent -1.7,-1.35 1.7,1.35, height 2.7
2512_WIDE [mm] "Ohmite recommended land pattern"
  rect 1x6.6 smd: 1(-1.6,0) 2(1.6,0)
  silkscreen extent -0.82,-3.32 0.82,3.35, body extent -1.65,-3.25 1.65,3.25, height 0.7
2512_WIDE_VISHAY [mm] "Vishay recommended land pattern"
  rect 1.9x7.6 smd: 1(-1.55,0) 2(1.55,0)
  silkscreen extent -0.3,-3.32 0.3,3.35, body extent -1.7,-3.25 1.7,3.25, height 0.9
AssemblyNote [mil] "Assembly Note"
AssemblyNoteLabel [mil] "Assembly Note for PCB Labels"
CR_1000x1270 [mm] "SMD, 2-Leads, Dia 10.5mm, Pin Spacing 8mm"
  rect 4x2 smd: 1(-4,0) 2(4,0)
  silkscreen extent -7.4,-5.25 5.25,5.25, body extent -5.25,-5.25 5.25,5.25, height 12.71
DNK0008A [mm] "SON, 8-Leads, Body 5x6mm"
  rrect39% 0.86x0.51 smd paste-0.05 mask-0.05: 1(-2.82,1.905) 2(-2.82,0.635) 3(-2.82,-0.635) 4(-2.82,-1.905) 5(2.82,-1.905) 6(2.82,-0.635) 7(2.82,0.635) 8(2.82,1.905)
  rrect8% 1.48x1.27 on Top Paste: 9(-0.18,1.47) 9(-0.18,0) 9(-0.18,-1.47) 9(1.5,-1.47) 9(1.5,0) 9(1.5,1.47)
  rrect5% 4.34x4.6 smd paste-3 mask-0.05: 9(1.08,0)
  silkscreen extent -3.2,-2.7 3.2,2.7, body extent -3.05,-2.55 3.05,2.55, height 1.06
Fiducial10-20 [mm]
  round 1 smd mask+0.5: 1(0,0)
  Top Layer keep-out circle w1.178: c0,0 r0.5
IEC_HotSurface_Small [mil]
  silkscreen extent -107,-93 107,92
Keystone575-8 [mm] "Banana Jack"
  round 10 hole 5.45: 1(0,0)
  body extent -3.92,-3.94 3.95,3.94, height 2.36
Keystone5005 [mil] "Keystone Compact loops"
  round 87 hole 63: 1(0,0)
  silkscreen extent -70,-70 70,70, body extent -63,-63 62,63, height 225
Keystone5006 [mil] "Keystone Compact loops"
  round 87 hole 63: 1(0,0)
  silkscreen extent -70,-70 70,70, body extent -63,-63 62,63, height 225
Keystone5007 [mil] "Keystone Compact loops"
  round 87 hole 63: 1(0,0)
  silkscreen extent -70,-70 70,70, body extent -63,-63 62,63, height 225
Keystone_1902C [mil] "Hex Standoff, 4-40 threaded, nylon"
  round 1 on Mech4: 0(0,0)
  body extent -145,-126 146,126, height 501
Label_650x200 [mil] "Thermal Transfer Label"
  round 1 on Mech13: 0(0,0)
  silkscreen extent -325,-100 325,100, body extent -325,-100 325,100, height 1
MTG_159mil [mil] "159mil Non Plated Hole"
  round 150 hole 159 unplated: 1(0,0)
PWP0028C_N [mm] "TSOP, 28-Leads, Body 9.7x4.4mm, Pitch 0.65mm, Exposed Pad, IPC Medium Density"
  rrect22% 1.4x0.45 smd: 1(-2.95,4.225) 2(-2.95,3.575) 3(-2.95,2.925) 4(-2.95,2.275) 5(-2.95,1.625) 6(-2.95,0.975) 7(-2.95,0.325) 8(-2.95,-0.325) 9(-2.95,-0.975) 10(-2.95,-1.625) 11(-2.95,-2.275) 12(-2.95,-2.925) 13(-2.95,-3.575) 14(-2.95,-4.225) 15(2.95,-4.225) 16(2.95,-3.575) 17(2.95,-2.925) 18(2.95,-2.275) 19(2.95,-1.625) 20(2.95,-0.975) 21(2.95,-0.325) 22(2.95,0.325) 23(2.95,0.975) 24(2.95,1.625) 25(2.95,2.275) 26(2.95,2.925) 27(2.95,3.575) 28(2.95,4.225)
  rrect3% 3.4x9.7 smd paste-1.7 mask-1.7: 29(0,0)
  rrect3% 3.1x5.18 on Bottom Paste: 29(0,0)
  rrect3% 3.1x5.18 on Bottom Solder: 29(0,0)
  silkscreen extent -3.5,-4.9 2,4.9, body extent -3.21,-4.85 3.21,4.85, height 0.98
SM_RADIAL_10AMM [mm] "10 x 7.9mm:  Sanyo Oscon F8"
  rect 4.4x1.9 smd: 1(-4.35,0) 2(4.35,0)
  silkscreen extent -5.25,-5.25 5.25,5.25, body extent -5.25,-5.25 5.25,5.25, height 8
SMA [mm] "Molded Diode, 2-Leads, Body 4.3x2.6mm, IPC Medium Density, based on OnSemi component dimensions and land pattern"
  rect 2x2 smd: 1(-2,0) 2(2,0)
  silkscreen extent -3.66,-1.57 2.79,1.57, body extent -2.6,-1.3 2.6,1.3, height 2.42
sod-323 [mm] "NXP recommended land pattern"
  rect 0.6x0.6 smd paste-0.05: 1(-1.1,0) 2(1.1,0)
  silkscreen extent -2.06,-0.86 1.53,0.86, body extent -1.3,-0.67 1.3,0.68, height 1.1
SOD-323F [mm] "NXP recommended land pattern"
  rect 0.6x0.6 smd paste-0.05: 1(-1.1,0) 2(1.1,0)
  silkscreen extent -2.06,-0.86 1.53,0.86, body extent -1.35,-0.67 1.35,0.67, height 0.79
SW_CJS_1201A [mm] "Copal- Electronics"
  rect 1x1.6 smd paste+0 mask+0.05: 1(-1.75,-1.15) 2(0,1.15) 3(1.75,-1.15)
  silkscreen extent -3,-1.6 -2.7,-0.8, body extent -3,-1.55 3,1.55, height 2.51
XAL1010 [mm] "COILCRAFT"
  rect 2.38x11.31 smd: 1(-3.325,0) 2(3.325,0)
  silkscreen extent -5.3,-6 5.3,6, body extent -5.25,-5.9 5.25,5.9, height 10
XAL1510 [mm] "COILCRAFT"
  rect 3.18x14.1 smd: 1(-5.3,0) 2(5.3,0)
  silkscreen extent -7.8,-8.3 7.8,8.2, body extent -7.7,-8.2 7.7,8.2, height 11

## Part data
C1 C31: "CAP, Aluminum Polymer, 100 µF, 63 V, +/- 20%, 0.024 ohm, SMD, 2-Leads, Dia 10.5mm, Pin Spacing 8mm SMD", Cap_Case=10x12.7mm, Manufacturer=Nichicon, Supplier Part Number 1=493-13783-1-ND, Tolerance_%=20, Value1="0.024 ohm", Value2=63V, ValueDisplayed=100µF
C2 C3 C4 C5 C32 C33 C34 C35 C36 C37 C38 C39: "CAP, CERM, 4.7 µF, 80 V, +/- 10%, X7R, 1210", Cap_Case=1210, Manufacturer=MuRata, Supplier Part Number 1=490-9972-1-ND, TempCo=X7R, Tolerance_%=10, Value1=Unknown, Value2=80V, ValueDisplayed=4.7µF
C6 C7 C8 C9 C10 C11: "CAP, CERM, 22 µF, 25 V, +/- 10%, X7R, 1210", Cap_Case=1210, Manufacturer=MuRata, Supplier Part Number 1=490-5313-1-ND, TempCo=X7R, Tolerance_%=10, Value1=Unknown, Value2=25V, ValueDisplayed=22µF
C12: "CAP, CERM, 1 µF, 25 V, +/- 10%, X7R, 0805", Cap_Case=0805, Manufacturer=MuRata, Supplier Part Number 1=GRM219R71E105KA88D-ND, TempCo=X7R, Tolerance_%=10, Value1=Unknown, Value2=25V, ValueDisplayed=1µF
C13 C14: "CAP, OS-CON, 330 µF, 16 V, +/- 20%, 0.016 ohm, 10x10.3 SMD", Cap_Case=10.3x10.3x12.6, Manufacturer=Sanyo, Supplier Part Number 1=9189084, Tolerance_%=20, Value1="0.016 ohm", Value2=16V, ValueDisplayed=330µF
C15: "CAP, CERM, 47pF, 50V, +/-5%, C0G/NP0, 0603", Cap_Case=0603, Manufacturer=MuRata, Supplier Part Number 1=490-1419-1-ND, TempCo=C0G/NP0, Tolerance_%=5, Value1=Unknown, Value2=50V, ValueDisplayed=47pF
C16: "CAP, CERM, 4.7 µF, 16 V, +/- 10%, X7R, 0805", Cap_Case=0805, Manufacturer=MuRata, Supplier Part Number 1=490-4522-1-ND, TempCo=X7R, Tolerance_%=10, Value1="0.006 ohm", Value2=16V, ValueDisplayed=4.7µF
C17 C21: "CAP, CERM, 0.1uF, 100V, +/-10%, X7R, 0603", Cap_Case=0603, Manufacturer=MuRata, Supplier Part Number 1=490-3285-1-ND, TempCo=X7R, Tolerance_%=10, Value1=Unknown, Value2=100V, ValueDisplayed=0.1µF
C18 C19 C25: "CAP, CERM, 0.22 µF, 25 V, +/- 10%, X7R, 0603", Cap_Case=0603, Manufacturer=MuRata, Supplier Part Number 1=490-3290-1-ND, TempCo=X7R, Tolerance_%=10, Value1=Unknown, Value2=25V, ValueDisplayed=0.22µF
C20 C30: "CAP, CERM, 100pF, 100V, +/-5%, C0G/NP0, 0603", Cap_Case=0603, Manufacturer=MuRata, Supplier Part Number 1=490-1351-1-ND, TempCo=C0G/NP0, Tolerance_%=5, Value1=Unknown, Value2=100V, ValueDisplayed=100pF
C22: "CAP, CERM, 0.033 µF, 50 V, +/- 10%, X7R, 0603", Cap_Case=0603, Manufacturer=MuRata, Supplier Part Number 1=490-3286-1-ND, TempCo=X7R, Tolerance_%=10, Value1=Unknown, Value2=50V, ValueDisplayed=0.033µF
C23 C26: library part GRM1885C1H470JA01D, "CAP, CERM, 47pF, 50V, +/-5%, C0G/NP0, 0603", Cap_Case=0603, Manufacturer=MuRata, Supplier Part Number 1=490-1419-1-ND, TempCo=C0G/NP0, Tolerance_%=5, Value1=Unknown, Value2=50V
C24: "CAP, CERM, 0.33 µF, 16 V, +/- 10%, X7R, 0603", Cap_Case=0603, Manufacturer=MuRata, Supplier Part Number 1=490-3294-1-ND, TempCo=X7R, Tolerance_%=10, Value1=Unknown, Value2=16V, ValueDisplayed=0.33µF
C27: "CAP, CERM, 0.022uF, 50V, +/-10%, X7R, 0603", Cap_Case=0603, Manufacturer=Kemet, Supplier Part Number 1=399-1280-1-ND, TempCo=X7R, Tolerance_%=10, Value1=Unknown, Value2=50V, ValueDisplayed=0.022µF
C28: "CAP, CERM, 1000 pF, 100 V, +/- 5%, C0G/NP0, 0603", Cap_Case=0603, Manufacturer=MuRata, Supplier Part Number 1=490-3281-1-ND, TempCo=C0G/NP0, Tolerance_%=5, Value1=Unknown, Value2=100V, ValueDisplayed=1000pF
C29: "CAP, CERM, 270 pF, 50 V, +/- 5%, C0G/NP0, 0603", Cap_Case=0603, Manufacturer=MuRata, Supplier Part Number 1=490-1437-1-ND, TempCo=C0G/NP0, Tolerance_%=5, Value1=Unknown, Value2=50V, ValueDisplayed=270pF
D1: library part RSX501L-20TE25, "Diode, Schottky, 20 V, 5 A, SMA", Manufacturer=Rohm, Supplier Part Number 1=RSX501L-20TE25CT-ND, Value1=5A, Value2=0.39V
D2: library part RB050L-60TE25, "Diode, Schottky, 60 V, 3 A, SMA", Manufacturer=Rohm, Supplier Part Number 1=RB050L-60TE25CT-ND, Value1=3A, Value2=0.56V
D3: library part PMEG6010CEJ,115, "Diode, Schottky, 60 V, 1 A, SOD-323F", Manufacturer="NXP Semiconductor", Supplier Part Number 1=568-4138-1-ND, Value1=1A, Value2=0.66V
D4 D5: library part BAS316,115, "Diode, Ultrafast, 100V, 0.25A, SOD-323", Manufacturer="NXP Semiconductor", Supplier Part Number 1=568-5003-1-ND, Value1=0.25A, Value2=1.4V
FID1 FID2 FID3: "Fiducial mark.  There is nothing to buy or mount.", Manufacturer=N/A
H5 H6 H7 H8: "Standoff, Hex, 0.5\"L #4-40 Nylon", Manufacturer=Keystone, Supplier Part Number 1=1902CK-ND
J1 J2 J3 J4: "Standard Banana Jack, Uninsulated, 8.9mm", Manufacturer=Keystone, Supplier Part Number 1=36-575-8-ND
L1: "Inductor, Shielded, Composite, 6.8 µH, 26 A, 0.00417 ohm, SMD", Manufacturer=Coilcraft, Value1="0.00417 ohm", Value2=26A, ValueDisplayed=6.8µH
L2: "Inductor, Shielded, Composite, 2.2 µH, 32 A, 0.00255 ohm, SMD", Manufacturer=Coilcraft, Supplier Part Number 1=994-XAL1010-222MEB, Value1="0.00255 ohm", Value2=32A, ValueDisplayed=2.2µH
LBL1: library part THT-14-423-10, "Thermal Transfer Printable Labels, 0.650\" W x 0.200\" H - 10,000 per roll", Manufacturer=Brady, Supplier Part Number 1=2065596
LOGO4 LOGO5: library part IEC_HotSurface, "IEC 61010-1 Hot Surface Warning"
MH1 MH2 MH3 MH4: library part "Mounting Hole (non-standard) No Pad", "PCB Mounting Hole, No Pad", Manufacturer=Any, PartNumber=N/A
Q1 Q2 Q3 Q4: "MOSFET, N-CH, 60 V, 172 A, DNK0008A (VSON-CLIP-8)", Alternate Manufacturer=None, Manufacturer="Texas Instruments", Supplier Part Number 1=296-35628-1-ND, Value1="3.3 ohm", Value2="27 nC"
Q5 Q6 Q7 Q8: "MOSFET, N-CH, 30 V, 100 A, DNK0008A (VSON-CLIP-8)", Alternate Manufacturer=None, Manufacturer="Texas Instruments", Supplier Part Number 1=CSD17573Q5B-ND, Value1="0.00145 ohm", Value2="49 nC"
R1 R7: "RES, 0.004, 1%, 3 W, 2512 WIDE", Manufacturer="Susumu Co Ltd", Power_W=3, Supplier Part Number 1=408-1614-1-ND, TempCo="50 ppm/C", Tolerance_%=1, Value1=1%, Value2=3W, Value_Code=4L000, ValueDisplayed=0.004
R2 R3 R4 R5 R12 R17 R24 R25 R26 R27: "RES, 0 ohm, 5%, 0.1W, 0603", Manufacturer="Yageo America", Power_W=0.1, Supplier Part Number 1=311-0.0GRCT-ND, TempCo="200 ppm/C", Tolerance_%=5, Value1=5%, Value2=0.1W, Value_Code=0000
R6 R8: "RES, 100 ohm, 1%, 0.1W, 0603", Manufacturer="Yageo America", Power_W=0.1, Supplier Part Number 1=311-100HRCT-ND, TempCo="200 ppm/C", Tolerance_%=1, Value1=1%, Value2=0.1W, Value_Code=100R
R9 R11: "RES, 10.0 ohm, 1%, 0.1W, 0603", Manufacturer="Yageo America", Power_W=0.1, Supplier Part Number 1=311-10.0HRCT-ND, TempCo="200 ppm/C", Tolerance_%=1, Value1=1%, Value2=0.1W, Value_Code=10R0
R10: "RES, 10.0k ohm, 1%, 0.1W, 0603", Manufacturer="Yageo America", Power_W=0.1, Supplier Part Number 1=311-10.0KHRCT-ND, TempCo="200 ppm/C", Tolerance_%=1, Value1=1%, Value2=0.1W, Value_Code=10k0
R13: "RES, 249k ohm, 1%, 0.1W, 0603", Manufacturer="Yageo America", Power_W=0.1, Supplier Part Number 1=311-249KHRCT-ND, TempCo="200 ppm/C", Tolerance_%=1, Value1=1%, Value2=0.1W, Value_Code=249k
R14: "RES, 280k ohm, 1%, 0.1W, 0603", Manufacturer="Yageo America", Power_W=0.1, Supplier Part Number 1=311-280KHRCT-ND, TempCo="200 ppm/C", Tolerance_%=1, Value1=1%, Value2=0.1W, Value_Code=280k
R15: "RES, 2.00 k, 1%, 0.1 W, 0603", Manufacturer=Vishay-Dale, Power_W=0.1, Supplier Part Number 1=541-2.00KHCT-ND, TempCo="100 ppm/C", Tolerance_%=1, Value1=1%, Value2=0.1W, Value_Code=2k00, ValueDisplayed=2.00k
R16 R21: library part RC0603FR-07100RL, "RES, 100 ohm, 1%, 0.1W, 0603", Manufacturer="Yageo America", Power_W=0.1, Supplier Part Number 1=311-100HRCT-ND, TempCo="200 ppm/C", Tolerance_%=1, Value1=1%, Value2=0.1W, Value_Code=100R
R18: "RES, 59.0k ohm, 1%, 0.1W, 0603", Manufacturer="Yageo America", Power_W=0.1, Supplier Part Number 1=311-59.0KHRCT-ND, TempCo="200 ppm/C", Tolerance_%=1, Value1=1%, Value2=0.1W, Value_Code=59k0
R19: "RES, 93.1 k, 1%, 0.1 W, 0603", Manufacturer="Yageo America", Power_W=0.1, Supplier Part Number 1=311-93.1KHRCT-ND, TempCo="200 ppm/C", Tolerance_%=1, Value1=1%, Value2=0.1W, Value_Code=93k1, ValueDisplayed=93.1k
R20: "RES, 33.2 k, 1%, 0.1 W, 0603", Manufacturer=Vishay-Dale, Power_W=0.1, Supplier Part Number 1=541-33.2KHCT-ND, TempCo="100 ppm/C", Tolerance_%=1, Value1=1%, Value2=0.1W, Value_Code=33k2, ValueDisplayed=33.2k
R22: "RES, 20.0k ohm, 1%, 0.1W, 0603", Manufacturer="Yageo America", Power_W=0.1, Supplier Part Number 1=311-20.0KHRCT-ND, TempCo="200 ppm/C", Tolerance_%=1, Value1=1%, Value2=0.1W, Value_Code=20k0
R23: "RES, 6.19 k, 1%, 0.1 W, 0603", Manufacturer=Vishay-Dale, Power_W=0.1, Supplier Part Number 1=541-6.19KHCT-ND, TempCo="100 ppm/C", Tolerance_%=1, Value1=1%, Value2=0.1W, Value_Code=6k19, ValueDisplayed=6.19k
R28: "RES, 0, 5%, 0.25 W, 1206", Manufacturer=Vishay-Dale, Power_W=0.25, Supplier Part Number 1=541-0.0ECT-ND, TempCo="200 ppm/C", Tolerance_%=5, Value1=5%, Value2=0.25W, Value_Code=0000, ValueDisplayed=0
R29: "RES, 0, 5%, 2 W, 2512 WIDE", Manufacturer="Vishay Draloric", Power_W=2, Supplier Part Number 1=RCL0.0ECT-ND, TempCo=ppm/C, Tolerance_%=5, Value1=5%, Value2=2W, Value_Code=0000, ValueDisplayed=0
S1 S2 S3: "Slide SW, SPDT 0.1A 50VDC", CurrentRating_mA=100, Manufacturer="Copal Electronics", Supplier Part Number 1=563-1023-1-ND
TP1 TP3: "Test Point, Compact, Red, TH", Manufacturer=Keystone, Supplier Part Number 1=5005K-ND
TP2 TP4: "Test Point, Compact, Black, TH", Manufacturer=Keystone, Supplier Part Number 1=5006K-ND
TP5 TP6 TP7: library part 5007, "Test Point, Compact, White, TH", Manufacturer=Keystone, Supplier Part Number 1=5007K-ND
U1: "55 V Wide VIN Synchronous 4-Switch Buck-Boost Controller, PWP0028C (TSSOP-28)", Alternate Manufacturer="Texas Instruments", Alternate PartNumber=LM5176PWPT
ZZ1: library part AssemblyNoteLabel, Alternate Manufacturer=-
ZZ2 ZZ3 ZZ4 ZZ5 ZZ6 ZZ7 ZZ8: library part AssemblyNote, Alternate Manufacturer=-

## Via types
v1: diameter 24, hole 10, Top Layer to Bottom Layer, tented both sides, 317 vias
v2: diameter 24, hole 10, Top Layer to Bottom Layer, 74 vias
v3: diameter 19.68, hole 7.87, Top Layer to Bottom Layer, tented both sides, 12 vias
v4: diameter 24, hole 14, Top Layer to Bottom Layer, 11 vias
v5: diameter 19.68, hole 7.87, Top Layer to Bottom Layer, 9 vias
v6: diameter 24, hole 14, Top Layer to Bottom Layer, tented both sides, 8 vias
v7: diameter 24, hole 10, Top Layer to Bottom Layer, tented top, 2 vias
v8: diameter 38, hole 24, Top Layer to Bottom Layer, 2 vias
v9: diameter 38, hole 24, Top Layer to Bottom Layer, tented both sides, 1 vias

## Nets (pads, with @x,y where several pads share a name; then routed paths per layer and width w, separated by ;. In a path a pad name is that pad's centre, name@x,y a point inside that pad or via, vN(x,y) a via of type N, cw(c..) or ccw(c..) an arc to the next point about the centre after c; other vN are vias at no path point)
BIAS: C25.1 R12.2 TP6.1 U1.24 | length 1416.3
  Top Layer w12: v1@1695.69,1855.69 C25.1@1758.62,1855.69
  MidLayer2 w12: v1(1695,1855) 1805,1745 1805,1625 1875,1555 v7(2210,1555)
  MidLayer3 w12: v1(1695,1855) 1760,1920 1760,2072.48 1822.52,2135 TP6.1@1885,2135 TP6.1@1885,2160
  Bottom Layer w12: v1@1695.39,1854.61 U1.24@1768.86,1854.61 U1.24@1772.8,1854.61 ; R12.2@2207.44,1410 2207.44,1552.44 v7(2210,1555)
CS: C15.1 R6.1 U1.16 | length 256.8
  Bottom Layer w12: C15.1@1645,1547.44 1645,1585 1709.88,1649.88 U1.16@1772.8,1649.88 ; R6.1@1647.44,1490.44 C15.1@1647.44,1555
CSG: C15.2 R8.1 U1.15 | length 176.2
  Bottom Layer w12: R8.1@1705,1507.56 1705,1610 1719.29,1624.29 U1.15@1772.8,1624.29
DITHER: C27.1 S3.2 U1.5 | length 926.7
  MidLayer3 w10: v1(2230,2013.43) 2288.43,1955 2670,1955 v1(2695,1980)
  Bottom Layer w10: U1.5@1997.2,1854.61 2115.35,1854.61 2131.38,1870.63 2131.38,1937.01 2207.8,2013.43 v1(2230,2013.43) C27.1@2274.64,2013.43 ; v1(2695,1980) S3.2@2740,1980
EN: C23.1 R13.1 R18.2 S2.2 U1.1 | length 908.9
  MidLayer3 w10: v1(2055,1960.63) 2159.37,2065 v1(2225,2065) 2555,2065 v1(2605,2115)
  Bottom Layer w10: U1.1@1997.2,1956.97 2051.34,1956.97 v1(2055,1960.63) ; v1(2225,2065) R18.2@2277.44,2065 C23.1@2277.44,2115 2277.44,2162.56 2275,2165 R13.1@2275,2192.44 ; v1(2605,2115) S2.2@2605,2169.72
FB: R14.1 R22.2 U1.11 | length 280.2
  Bottom Layer w10: U1.11@1997.2,1701.06 2184.57,1701.06 2195,1690.63 R22.2@2222.38,1690.63 R22.2@2222.38,1690.63 R14.1@2222.44,1640
GND: C2.2 C3.2 C4.2 C5.2 C6.2 C7.2 C8.2 C9.2 C10.2 C11.2 C12.2 C13.2 C14.2 C16.1 C17.2 C21.2 C23.2 C25.2 C26.2 C27.2 C28.2 C29.2 C30.2 C31.2 C32.2 C33.2 C34.2 C35.2 C36.2 C37.2 C38.2 C39.2 J2.1 J4.1 R7.1 R8.2 R18.1 R19.1 R20.1 R22.1 R23.1 R28.1 S1.1 S2.1 S3.1 TP2.1 TP4.1 U1.10 U1.22 U1.29@1885,1790.63 | length 1807.8
  Top Layer w10: v1(1390,1801.16) 1432.67,1801.16 R7.1@1434.36,1799.47
  Bottom Layer w10: v1(1390,1801.16) 1377.87,1789.03 1377.87,1642.13 1565.83,1454.17 1624.63,1454.17 ; R8.2@1699.17,1454.17 1665.37,1454.17 ; 1624.67,1454.13 1665.33,1454.13 ; 1624.63,1454.17 1624.67,1454.13 ; 1665.33,1454.13 1665.37,1454.17
  Bottom Layer w12: 1708.43,1803.43 U1.29@1872.2,1803.43 ; U1.29@1930,1726.65 2045,1726.65
  Bottom Layer w16: v1@1655,1780 1678.43,1803.43 1708.43,1803.43 ; 2045,1726.65 2321.02,1726.65 2325,1730.63
  Bottom Layer w24: C16.1@1575,1780 v1(1645,1780) v1@1655,1780 ; 2530,1960 2638.98,1960 2693.7,1905.28 S1.1@2781.1,1905.28 ; 2530,2075 2534.72,2070.28 S3.1@2671.1,2070.28 ; 2536.1,2181.1 S2.1@2536.1,2260.28
  other v1: 1280,1220 1330,1220 1380,1220 1430,1220 1480,1220 1530,1220 1580,1220 1630,1220 1680,1220 1730,1220 1780,1220 1330,1270 1380,1270 1430,1270 1480,1270 1530,1270 1580,1270 1630,1270 1680,1270 1730,1270 1780,1270 1410,1305 1455,1305 1500,1305 2140,1340 2330,1340 2380,1340 2435,1340 2490,1340 2585,1340 1410,1355 1455,1355 1500,1355 2945,1390 2995,1390 3045,1390 1410,1405 1455,1405 1500,1405 2945,1440 2995,1440 3045,1440 1455,1455 2945,1490 2995,1490 3040,1490 1558.01,1518.03 2945,1540 2995,1540 3045,1540 2945,1590 2995,1590 3045,1590 1405,1655 1400,1705 1400,1750 1400,1850 1400,1900 1405,1950 1405,2000 1520,2005 2945,2035 2995,2035 3045,2035 1480,2040 1440,2075 2945,2080 2995,2080 3045,2080 1405,2115 2945,2130 2995,2130 3045,2130 2945,2180 2995,2180 3040,2180 1555,2190 2190,2215 2945,2230 2995,2230 3045,2230 1505,2240 1555,2240 2395,2240 2440,2240 2486.89,2240 1460,2285 1505,2285 1555,2285 1405,2330 1455,2330 1505,2330 1555,2330 1605,2330 1655,2330 1705,2330 1755,2330 1805,2330 1355,2380 1405,2380 1455,2380 1505,2380 1555,2380 1605,2380 1655,2380 1705,2380 1755,2380 1805,2380
  other v3: 1833.82,1633.15 1885,1633.15 1936.18,1633.15 1833.82,1684.33 1885,1684.33 1936.18,1684.33 1833.82,1896.93 1885,1896.93 1936.18,1896.93 1833.82,1948.11 1885,1948.11 1936.18,1948.11
  other v5: 1833.82,1739.45 1885,1739.45 1936.18,1739.45 1833.82,1790.63 1885,1790.63 1936.18,1790.63 1833.82,1841.81 1885,1841.81 1936.18,1841.81
HO1: R2.2 R3.2 U1.27 | length 1088.2
  MidLayer3 w24: v4@905,2427.44 905,2426.95 v4(1195,2426.95) 1233.13,2426.95 1695,1965.08 v6(1695,1940)
  Bottom Layer w12: v6(1695,1940) 1703.62,1931.38 U1.27@1772.8,1931.38
  other v4: 900,2427.44
HO2: R24.2 R25.2 U1.19 | length 1017.1
  MidLayer3 w24: v4(1135.08,1195) 1584.32,1644.24 1584.32,1644.32 1597.44,1657.44 1617.44,1657.44 v6(1675,1715)
  Bottom Layer w12: v6(1675,1715) 1686.65,1726.65 U1.19@1772.8,1726.65
  Bottom Layer w24: R25.2@1082.56,1135 1125,1135 1135.08,1145.08 v4(1135.08,1195) R24.2@1082.56,1195
LO1: R4.2 R5.2 U1.25 | length 798.4
  MidLayer3 w24: v6(1370,2085) 1570,1885 v6(1660,1885)
  Bottom Layer w12: v6(1660,1885) 1660.75,1884.25 1715,1884.25 1719.06,1880.2 U1.25@1772.8,1880.2
  Bottom Layer w24: R5.2@1185,2187.56 1185,2220 ; R4.2@1185,2257.44 1185,2220 ; v6(1370,2085) 1235,2220 1185,2220
LO2: R26.2 R27.2 U1.21 | length 758.1
  MidLayer3 w24: v6@1370,1549.86 1567.01,1746.87 1666.87,1746.87 v6(1695,1775)
  Bottom Layer w12: v6@1697.83,1777.83 U1.21@1772.8,1777.83
  Bottom Layer w24: R26.2@1185,1512.56 1185,1550 ; R27.2@1185,1592.44 1185,1550 ; v6(1370,1550) 1185,1550
MODE: C26.1 R19.2 S1.2 U1.4 | length 1046.7
  MidLayer3 w10: v1(2065,1880.63) 2584.37,1880.63 v1(2650,1815)
  Bottom Layer w10: U1.4@1997.2,1880.2 2064.57,1880.2 v1(2065,1880.63) ; R19.2@2582.56,1920.63 C26.1@2582.56,1870.63 2639.37,1870.63 2650,1860 v1(2650,1815) S1.2@2849.72,1815
NetC1_2: C1.2 R28.2 | length 316.7
  Top Layer w40: C1.2@2020,2492.52 2143.7,2492.52 2208.27,2557.09 R28.2@2310,2557.09
NetC17_1: C17.1 R9.1 U1.2 | length 290.6
  Bottom Layer w12: U1.2@1997.2,1931.38 2065.75,1931.38 2080.87,1946.5 2080.87,1983.93 2075,1989.8 2075,2030.63 2065,2040.63 C17.1@2015,2040.63 ; C17.1@2015,2043.07 R9.1@2015,2093.07
NetC18_2: C18.2 D4.1 U1.26 | length 312.6
  Bottom Layer w12: D4.1@1475,1938.31 1546.69,1938.31 1557.56,1927.44 C18.2@1595,1927.44 1667.56,1927.44 1690.87,1904.13 1771.13,1904.13 U1.26@1772.8,1905.79
NetC19_1: C19.1 D5.1 U1.20 | length 318.7
  Bottom Layer w12: D5.1@1475,1701.69 1546.69,1701.69 1557.56,1712.56 C19.1@1590,1712.56 1632.56,1712.56 1669.13,1749.13 1714.13,1749.13 1717.24,1752.24 U1.20@1772.8,1752.24
NetC20_1: C20.1 TP7.1 | length 241.6
  Bottom Layer w10: C20.1@2580,1717.44 2580,1600 TP7.1@2667.82,1512.18
NetC20_2: C20.2 R20.2 U1.6 | length 847.9
  MidLayer2 w10: v1(2207.8,1963.43) 2228.46,1942.76 2462.24,1942.76 v1(2580,1825)
  Bottom Layer w10: U1.6@1997.2,1829.02 2129.4,1829.02 2149.25,1848.87 2149.25,1904.88 v1(2207.8,1963.43) R20.2@2274.64,1963.43 ; C20.2@2580,1772.56 v1(2580,1825)
NetC21_1: C21.1 U1.8 | length 343.8
  Bottom Layer w10: U1.8@1997.2,1777.83 2162.2,1777.83 2185,1800.63 2185,1850.63 2195,1860.63 C21.1@2277.44,1860.63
